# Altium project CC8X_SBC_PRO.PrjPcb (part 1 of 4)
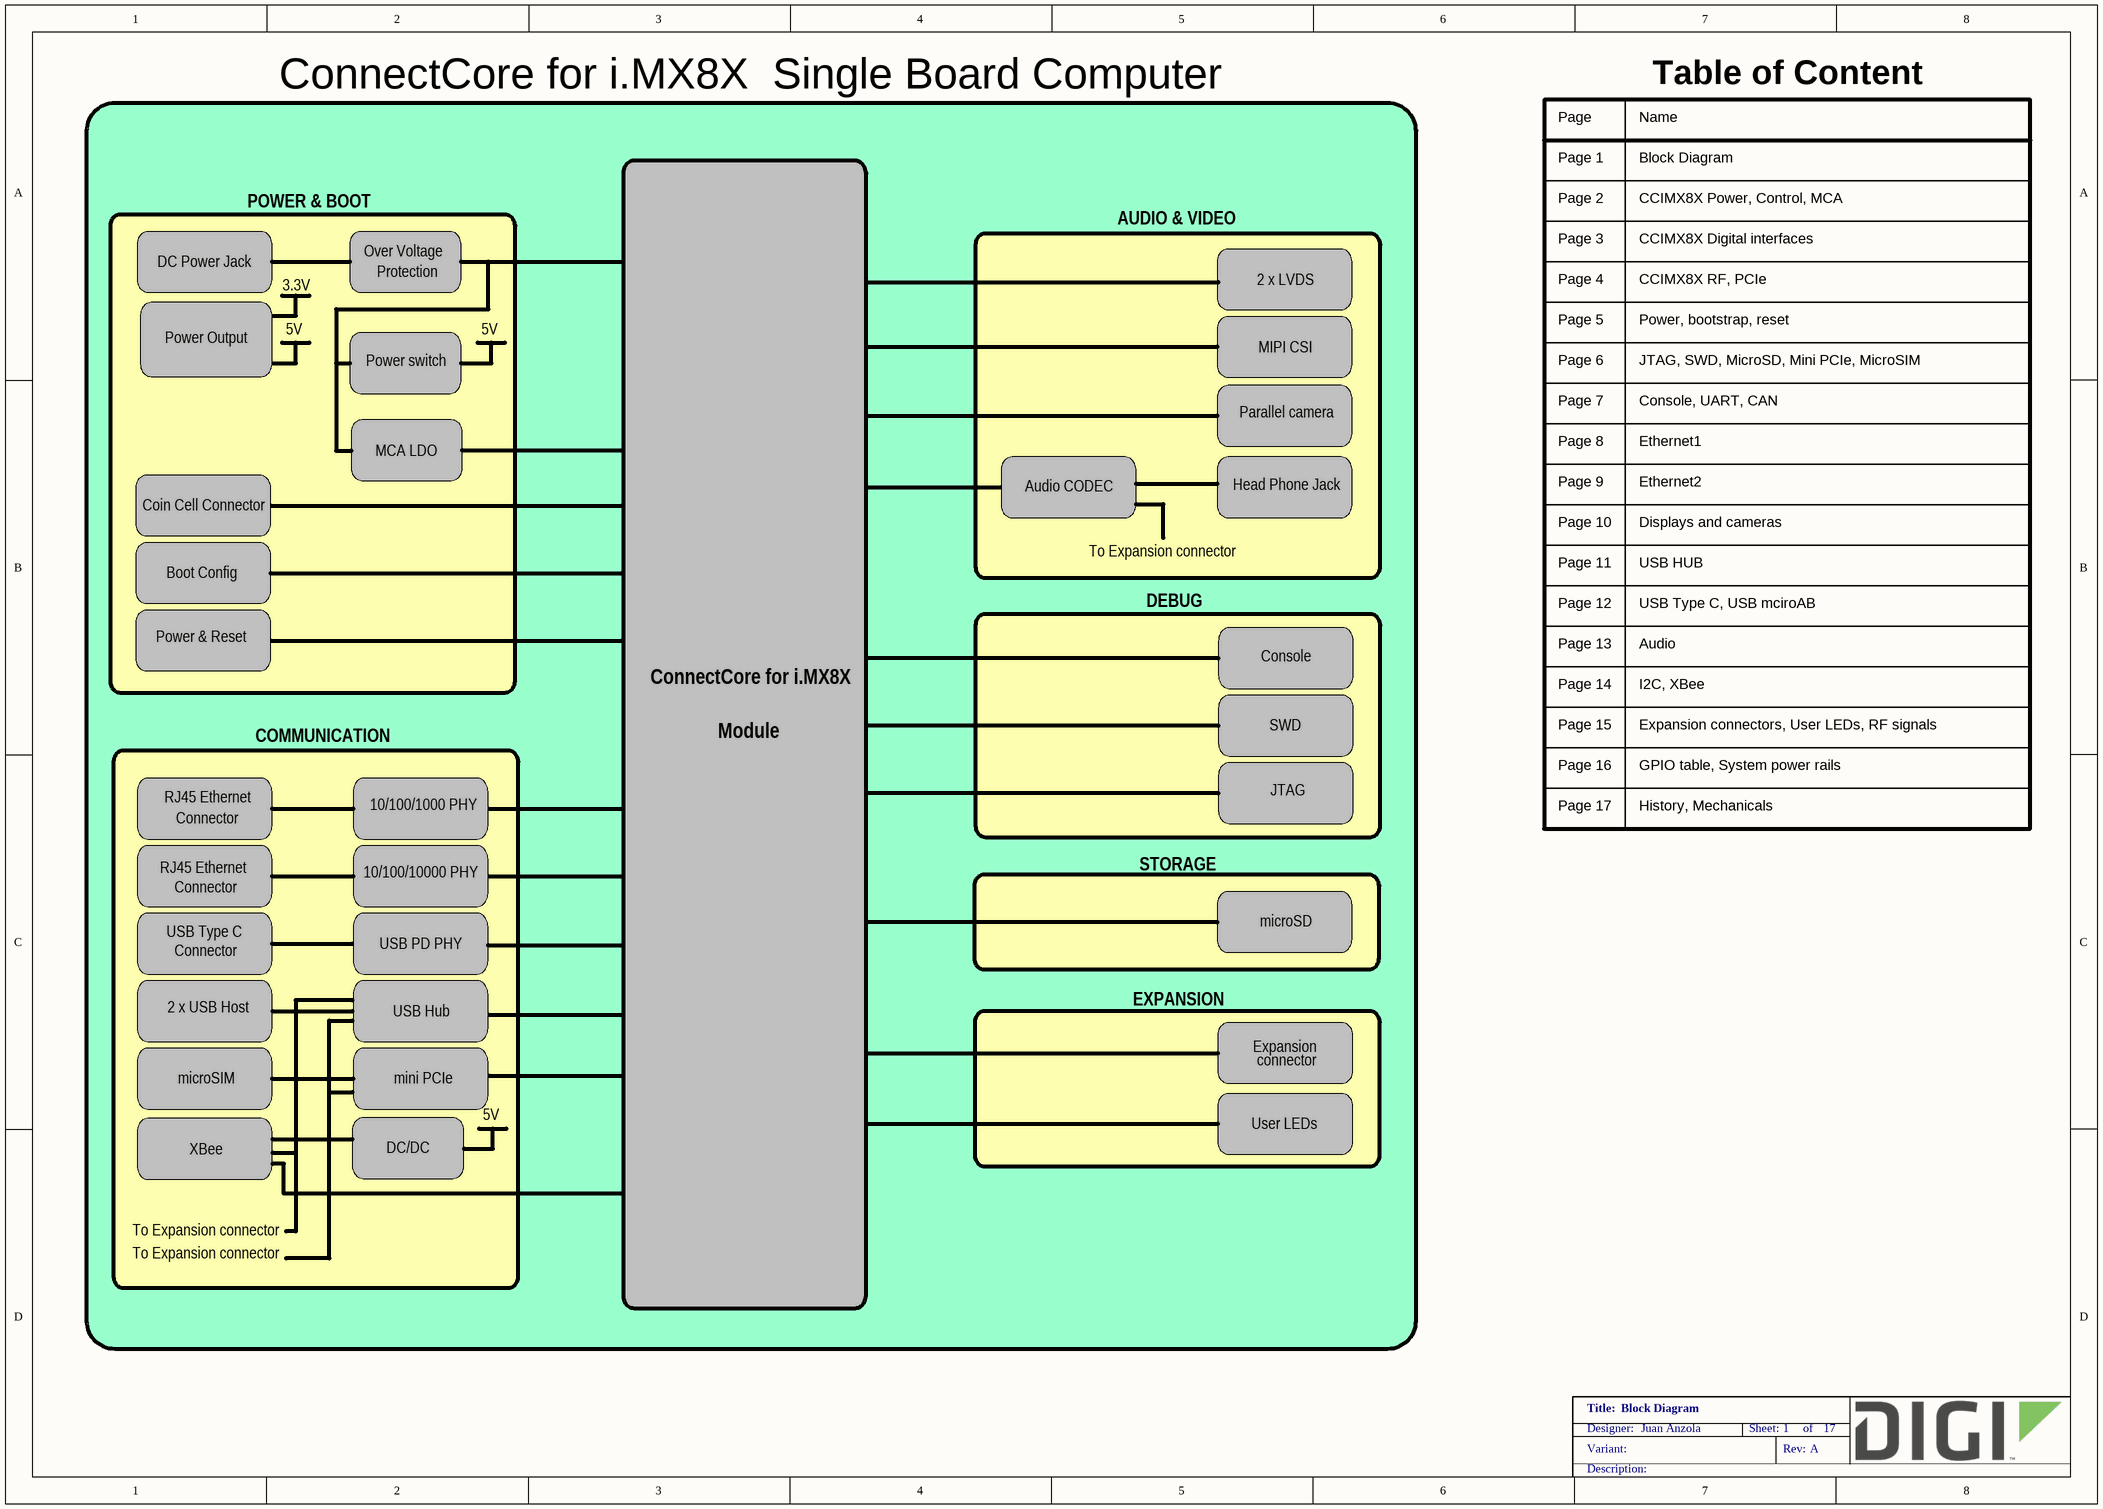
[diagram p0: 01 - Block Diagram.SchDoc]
VariantRevision: A
17 sheets, 578 parts. Net scope: flat (ports and power ports of the same name join across sheets).
Board file: 30015752-05_A.PcbDoc
Sheets:
  01 - Block Diagram.SchDoc
  02 - CCIMX8X Power, Control, MCA.SchDoc
  03 - CCIMX8X Digital interfaces.SchDoc
  04 - CCIMX8X RF, PCIe.SchDoc
  05 - Power, bootstrap, reset.SchDoc
  06 - JTAG, SWD, MicroSD, Mini PCIe, MicroSIM.SchDoc
  07 - Console, UART, CAN.SchDoc
  08 - Ethernet1.SchDoc
  09 - Ethernet2.SchDoc
  10 - Displays and cameras.SchDoc
  11 - USB HUB.SchDoc
  12 - USB Type C, USB microAB.SchDoc
  13 - Audio.SchDoc
  14 - I2C, XBee.SchDoc
  15 - Expansion connectors, User LEDs, RF signals.SchDoc
  16 - GPIO Table, System power rails.SchDoc
  17 - History, Mechanicals.SchDoc

## Sheet 01 - Block Diagram.SchDoc: Block Diagram
size A3; PageSetup: Record=PageOptions¦CenterHorizontal=True¦CenterVertical=True¦PrintScale=0.70¦XCorrection=1.00¦YCorrection=1.00¦PrintKind=0¦BorderSize=5000000¦LeftOffset=0¦BottomOffset=0¦Orientation=2¦PaperLength=4200¦PaperWidth=2970¦Scale=100¦PaperSource=7¦PrintQuality=600¦MediaType=1¦DitherType=10¦PaperKind=A4¦PrintScaleMode=1; Author: Juan Anzola; SheetNumber: 1; SheetTotal: 17

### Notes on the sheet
- ConnectCore for i.MX8X  Single Board Computer
- Table of Content
- Page 1
- Page
- Block Diagram
- Name
- POWER & BOOT
- AUDIO & VIDEO
- Page 2
- Page 3
- CCIMX8X Power, Control, MCA
- CCIMX8X Digital interfaces
- DC Power Jack
- 3.3V
- Protection
- Over Voltage
- 2 x LVDS
- Page 4
- CCIMX8X RF, PCIe
- Power Output
- 5V
- Power switch
- MIPI CSI
- Page 5
- Page 6
- JTAG, SWD, MicroSD, Mini PCIe, MicroSIM
- Power, bootstrap, reset
- Parallel camera
- Page 7
- Page 8
- Ethernet1
- Console, UART, CAN
- Coin Cell Connector
- MCA LDO
- Audio CODEC
- Head Phone Jack
- Page 9
- Ethernet2
- Boot Config
- To Expansion connector
- Page 10
- Page 11
- Displays and cameras
- USB HUB
- Power & Reset
- DEBUG
- Page 12
- Page 13
- Audio
- USB Type C, USB mciroAB
- ConnectCore for i.MX8X
- Console
- Page 14
- I2C, XBee
- COMMUNICATION
- Module
- SWD
- Page 15
- Page 16
- Expansion connectors, User LEDs, RF signals
- GPIO table, System power rails
- RJ45 Ethernet
- Connector
- 10/100/1000 PHY
- JTAG
- Page 17
- History, Mechanicals
- 10/100/10000 PHY
- STORAGE
- USB Type C
- USB PD PHY
- microSD
- 2 x USB Host
- USB Hub
- EXPANSION
- Expansion
- microSIM
- mini PCIe
- connector
- XBee
- DC/DC
- User LEDs

## Sheet 02 - CCIMX8X Power, Control, MCA.SchDoc: CCIMX8X Power, Control, MCA
size A3; PageSetup: Record=PageOptions¦CenterHorizontal=True¦CenterVertical=True¦PrintScale=0.70¦XCorrection=1.00¦YCorrection=1.00¦PrintKind=0¦BorderSize=5000000¦LeftOffset=0¦BottomOffset=0¦Orientation=2¦PaperLength=4200¦PaperWidth=2970¦Scale=100¦PaperSource=7¦PrintQuality=600¦MediaType=1¦DitherType=10¦PaperKind=A4¦PrintScaleMode=1; Author: Juan Anzola; SheetNumber: 2; SheetTotal: 17
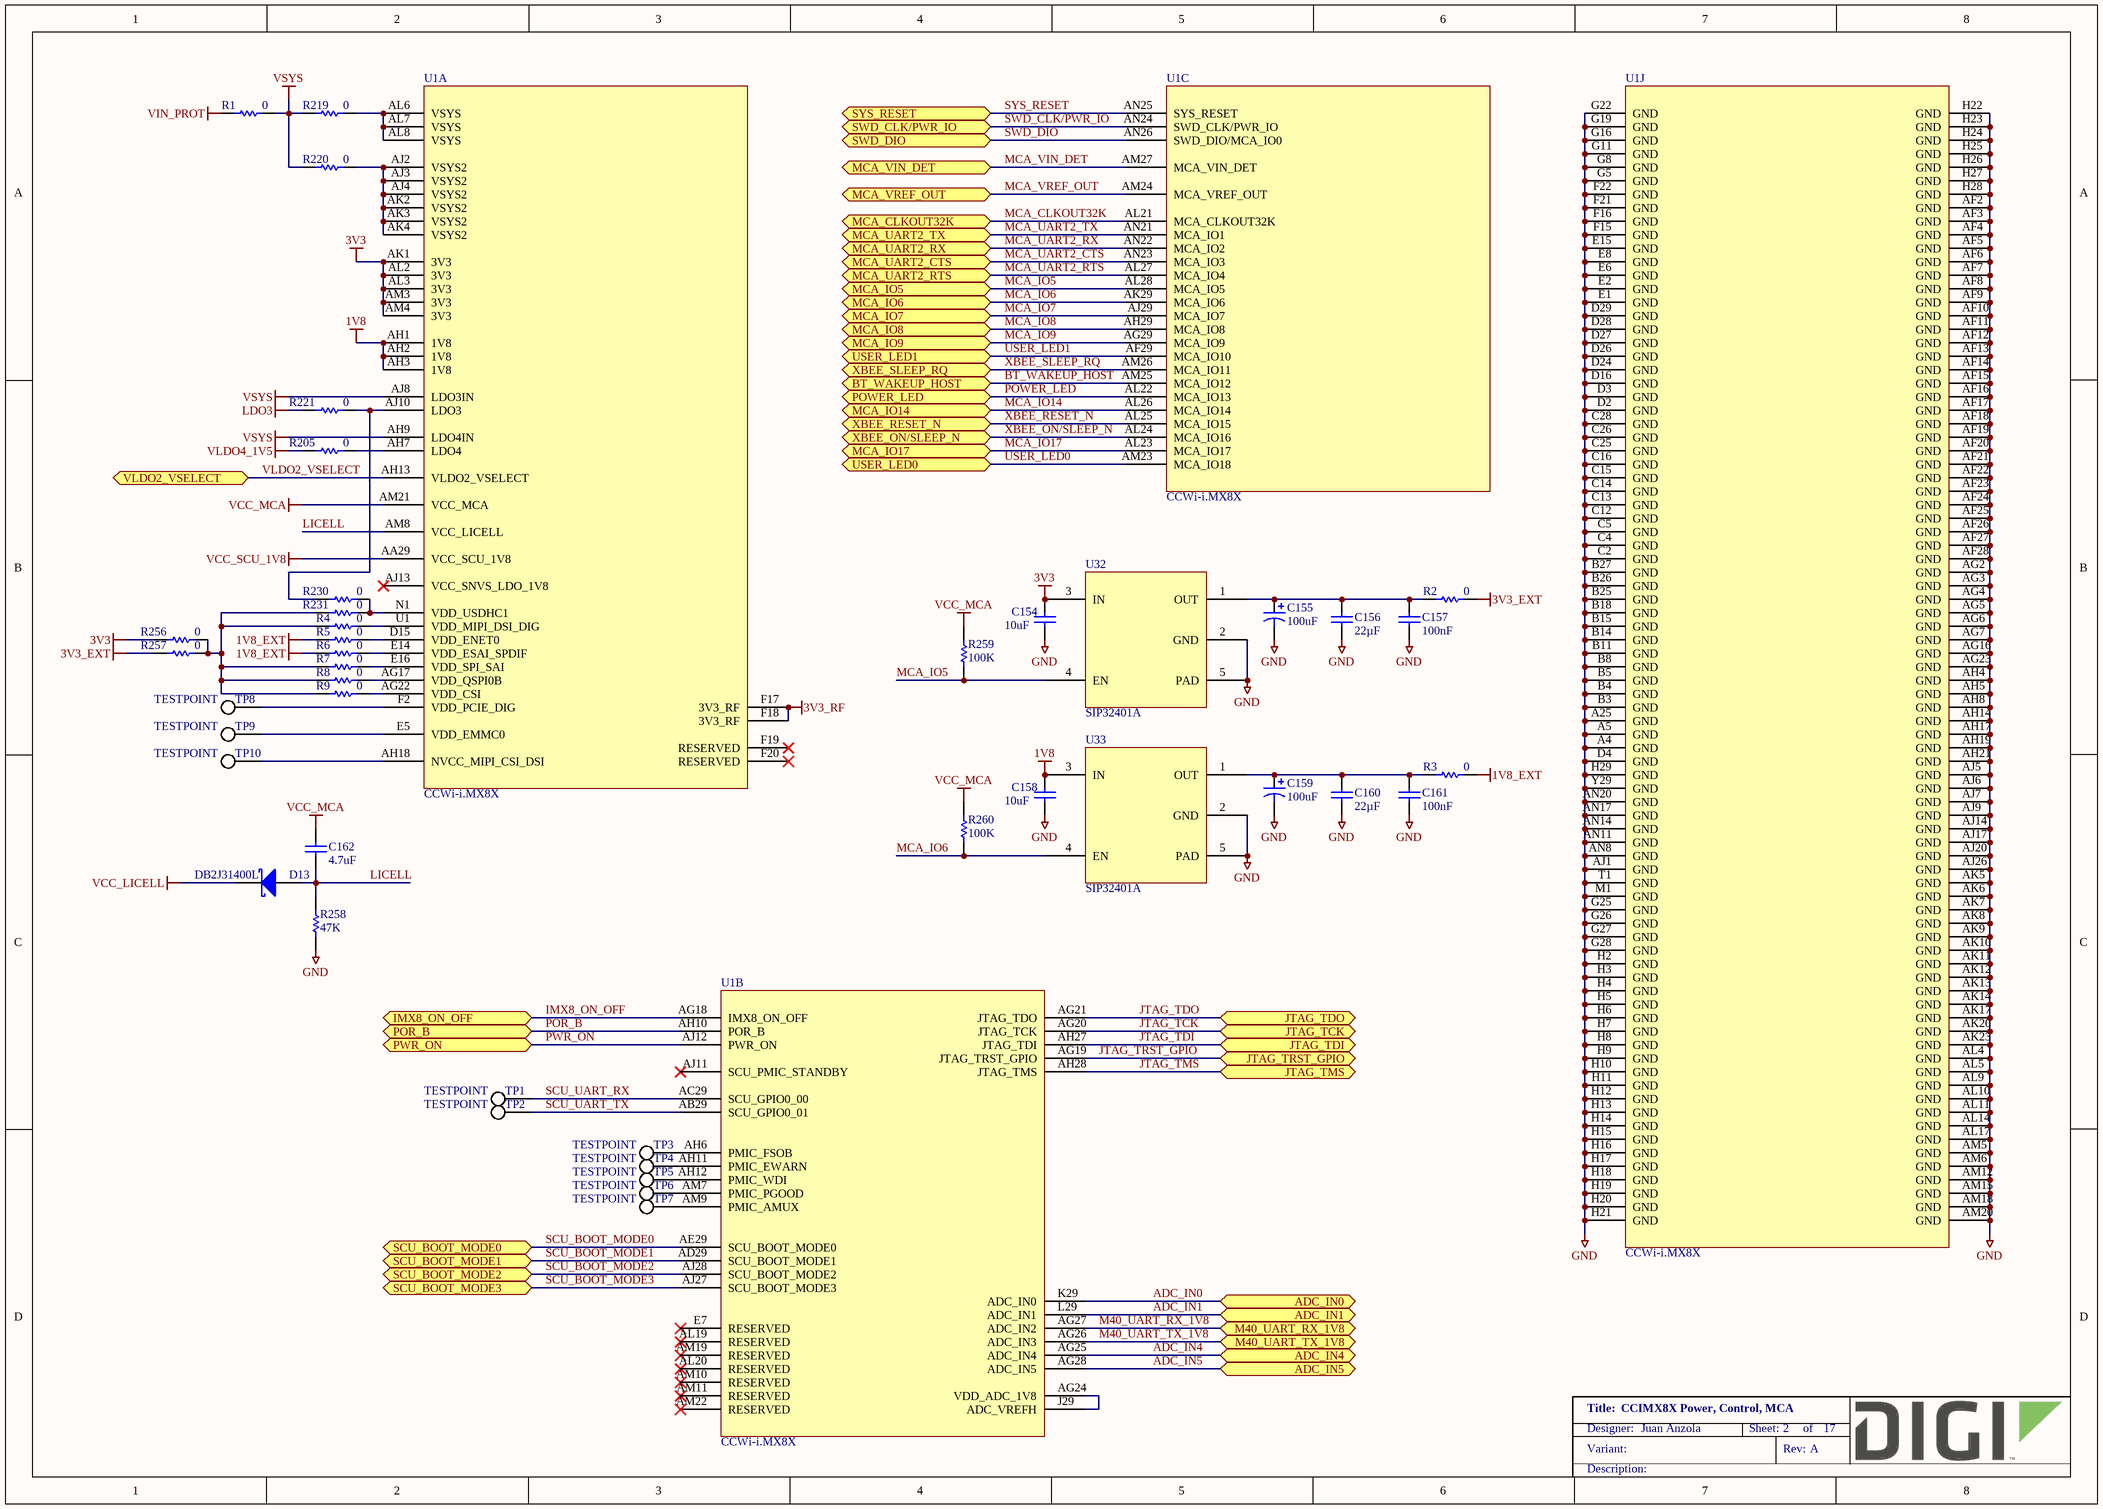
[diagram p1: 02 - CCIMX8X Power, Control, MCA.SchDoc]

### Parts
C154  10uF  [CAPC1005X55N]
C155  100uF  [CAPMP3216X120N]
C156  22µF  [CAPC1608X90N]
C157  100nF  [CAPC1005X55N]
C158  10uF  [CAPC1005X55N]
C159  100uF  [CAPMP3216X120N]
C160  22µF  [CAPC1608X90N]
C161  100nF  [CAPC1005X55N]
C162  4.7uF  [CAPC1005X55N]
D13  DB2J31400L  [SODFL2513X80N]
R1  0  [RESC2013X70N]
R2  0  [RESC1005X40N]
R3  0  [RESC1005X40N]
R4  0  [RESC1005X40N]
R5  0  [RESC1005X40N]
R6  0  [RESC1005X40N]
R7  0  [RESC1005X40N]
R8  0  [RESC1005X40N]
R9  0  [RESC1005X40N]
R205  0  [RESC1005X40N]
R219  0  [RESC1609X55N]
R220  0  [RESC1609X55N]
R221  0  [RESC1005X40N]
R230  0  [RESC1005X40N]
R231  0  [RESC1005X40N]
R256  0  [RESC1005X40N]
R257  0  [RESC1005X40N]
R258  47K  [RESC1005X40N]
R259  100K  [RESC1005X40N]
R260  100K  [RESC1005X40N]
TP1  TESTPOINT  [TP0762]  (no BOM)
TP2  TESTPOINT  [TP0762]  (no BOM)
TP3  TESTPOINT  [TP0762]  (no BOM)
TP4  TESTPOINT  [TP0762]  (no BOM)
TP5  TESTPOINT  [TP0762]  (no BOM)
TP6  TESTPOINT  [TP0762]  (no BOM)
TP7  TESTPOINT  [TP0762]  (no BOM)
TP8  TESTPOINT  [TP0762]  (no BOM)
TP9  TESTPOINT  [TP0762]  (no BOM)
TP10  TESTPOINT  [TP0762]  (no BOM)
U1  CCWi-i.MX8X  [CC8X_LGA]  (parts A,B,C,J of 10)
U32  SIP32401A  [SON50P120X160X60-5T55X91N]
U33  SIP32401A  [SON50P120X160X60-5T55X91N]

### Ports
ADC_IN0 (bidir), ADC_IN1 (bidir), ADC_IN4 (bidir), ADC_IN5 (bidir), BT_WAKEUP_HOST (bidir), IMX8_ON_OFF (bidir), JTAG_TCK (bidir), JTAG_TDI (bidir), JTAG_TDO (bidir), JTAG_TMS (bidir), JTAG_TRST_GPIO (bidir), M40_UART_RX_1V8 (bidir), M40_UART_TX_1V8 (bidir), MCA_CLKOUT32K (bidir), MCA_IO5 (bidir), MCA_IO6 (bidir), MCA_IO7 (bidir), MCA_IO8 (bidir), MCA_IO9 (bidir), MCA_IO14 (bidir), MCA_IO17 (bidir), MCA_UART2_CTS (bidir), MCA_UART2_RTS (bidir), MCA_UART2_RX (bidir), MCA_UART2_TX (bidir), MCA_VIN_DET (bidir), MCA_VREF_OUT (bidir), POR_B (bidir), POWER_LED (bidir), PWR_ON (bidir), SCU_BOOT_MODE0 (bidir), SCU_BOOT_MODE1 (bidir), SCU_BOOT_MODE2 (bidir), SCU_BOOT_MODE3 (bidir), SWD_CLK/PWR_IO (bidir), SWD_DIO (bidir), SYS_RESET (bidir), USER_LED0 (bidir), USER_LED1 (bidir), VLDO2_VSELECT (bidir), XBEE_ON/SLEEP_N (bidir), XBEE_RESET_N (bidir), XBEE_SLEEP_RQ (bidir)

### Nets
1V8: C158.2 U1.AH1(1V8) U1.AH2(1V8) U1.AH3(1V8) U33.3(IN)
1V8_EXT: R3.1 R5.1 R6.1
3V3: C154.2 R256.2 U1.AK1(3V3) U1.AL2(3V3) U1.AL3(3V3) U1.AM3(3V3) U1.AM4(3V3) U32.3(IN)
3V3_EXT: R2.1 R257.1
3V3_RF: U1.F17(3V3_RF) U1.F18(3V3_RF)
GND: C154.1 C155.2 C156.1 C157.1 C158.1 C159.2 C160.1 C161.1 R258.1 U1.A4(GND) U1.A5(GND) U1.A25(GND) U1.AF2(GND) U1.AF3(GND) U1.AF4(GND) U1.AF5(GND) U1.AF6(GND) U1.AF7(GND) U1.AF8(GND) U1.AF9(GND) U1.AF10(GND) U1.AF11(GND) U1.AF12(GND) U1.AF13(GND) U1.AF14(GND) U1.AF15(GND) U1.AF16(GND) U1.AF17(GND) U1.AF18(GND) U1.AF19(GND) U1.AF20(GND) U1.AF21(GND) U1.AF22(GND) U1.AF23(GND) U1.AF24(GND) U1.AF25(GND) U1.AF26(GND) U1.AF27(GND) U1.AF28(GND) U1.AG2(GND) U1.AG3(GND) U1.AG4(GND) U1.AG5(GND) U1.AG6(GND) U1.AG7(GND) U1.AG16(GND) U1.AG23(GND) U1.AH4(GND) U1.AH5(GND) U1.AH8(GND) U1.AH14(GND) U1.AH17(GND) U1.AH19(GND) U1.AH21(GND) U1.AJ1(GND) U1.AJ5(GND) U1.AJ6(GND) U1.AJ7(GND) U1.AJ9(GND) U1.AJ14(GND) U1.AJ17(GND) U1.AJ20(GND) U1.AJ26(GND) U1.AK5(GND) U1.AK6(GND) U1.AK7(GND) U1.AK8(GND) U1.AK9(GND) U1.AK10(GND) U1.AK11(GND) U1.AK12(GND) U1.AK13(GND) U1.AK14(GND) U1.AK17(GND) U1.AK20(GND) U1.AK23(GND) U1.AL4(GND) U1.AL5(GND) U1.AL9(GND) U1.AL10(GND) U1.AL11(GND) U1.AL14(GND) U1.AL17(GND) U1.AM5(GND) U1.AM6(GND) U1.AM12(GND) U1.AM15(GND) U1.AM18(GND) U1.AM20(GND) U1.AN8(GND) U1.AN11(GND) U1.AN14(GND) U1.AN17(GND) U1.AN20(GND) U1.B3(GND) U1.B4(GND) U1.B5(GND) U1.B8(GND) U1.B11(GND) U1.B14(GND) U1.B15(GND) U1.B18(GND) U1.B25(GND) U1.B26(GND) U1.B27(GND) U1.C2(GND) U1.C4(GND) U1.C5(GND) U1.C12(GND) U1.C13(GND) U1.C14(GND) U1.C15(GND) U1.C16(GND) U1.C25(GND) U1.C26(GND) U1.C28(GND) U1.D2(GND) U1.D3(GND) U1.D4(GND) U1.D16(GND) U1.D24(GND) U1.D26(GND) U1.D27(GND) U1.D28(GND) U1.D29(GND) U1.E1(GND) U1.E2(GND) U1.E6(GND) U1.E8(GND) U1.E15(GND) U1.F15(GND) U1.F16(GND) U1.F21(GND) U1.F22(GND) U1.G5(GND) U1.G8(GND) U1.G11(GND) U1.G16(GND) U1.G19(GND) U1.G22(GND) U1.G25(GND) U1.G26(GND) U1.G27(GND) U1.G28(GND) U1.H2(GND) U1.H3(GND) U1.H4(GND) U1.H5(GND) U1.H6(GND) U1.H7(GND) U1.H8(GND) U1.H9(GND) U1.H10(GND) U1.H11(GND) U1.H12(GND) U1.H13(GND) U1.H14(GND) U1.H15(GND) U1.H16(GND) U1.H17(GND) U1.H18(GND) U1.H19(GND) U1.H20(GND) U1.H21(GND) U1.H22(GND) U1.H23(GND) U1.H24(GND) U1.H25(GND) U1.H26(GND) U1.H27(GND) U1.H28(GND) U1.H29(GND) U1.M1(GND) U1.T1(GND) U1.Y29(GND) U32.2(GND) U32.5(PAD) U33.2(GND) U33.5(PAD)
LDO3: R221.1
VCC_LICELL: D13.K
VCC_MCA: C162.2 R259.2 R260.2 U1.AM21(VCC_MCA)
VCC_SCU_1V8: U1.AA29(VCC_SCU_1V8)
VIN_PROT: R1.1
VLDO4_1V5: R205.1
VSYS: R1.2 R219.1 R220.1 U1.AH9(LDO4IN) U1.AJ8(LDO3IN)
ADC_IN0: U1.K29(ADC_IN0) ; port ADC_IN0
ADC_IN1: U1.L29(ADC_IN1) ; port ADC_IN1
ADC_IN4: U1.AG25(ADC_IN4) ; port ADC_IN4
ADC_IN5: U1.AG28(ADC_IN5) ; port ADC_IN5
BT_WAKEUP_HOST: U1.AM25(MCA_IO12) ; port BT_WAKEUP_HOST
IMX8_ON_OFF: U1.AG18(IMX8_ON_OFF) ; port IMX8_ON_OFF
JTAG_TCK: U1.AG20(JTAG_TCK) ; port JTAG_TCK
JTAG_TDI: U1.AH27(JTAG_TDI) ; port JTAG_TDI
JTAG_TDO: U1.AG21(JTAG_TDO) ; port JTAG_TDO
JTAG_TMS: U1.AH28(JTAG_TMS) ; port JTAG_TMS
JTAG_TRST_GPIO: U1.AG19(JTAG_TRST_GPIO) ; port JTAG_TRST_GPIO
LICELL: C162.1 D13.A R258.2 U1.AM8(VCC_LICELL)
M40_UART_RX_1V8: U1.AG27(ADC_IN2) ; port M40_UART_RX_1V8
M40_UART_TX_1V8: U1.AG26(ADC_IN3) ; port M40_UART_TX_1V8
MCA_CLKOUT32K: U1.AL21(MCA_CLKOUT32K) ; port MCA_CLKOUT32K
MCA_IO5: R259.1 U1.AL28(MCA_IO5) U32.4(EN) ; port MCA_IO5
MCA_IO6: R260.1 U1.AK29(MCA_IO6) U33.4(EN) ; port MCA_IO6
MCA_IO7: U1.AJ29(MCA_IO7) ; port MCA_IO7
MCA_IO8: U1.AH29(MCA_IO8) ; port MCA_IO8
MCA_IO9: U1.AG29(MCA_IO9) ; port MCA_IO9
MCA_IO14: U1.AL26(MCA_IO14) ; port MCA_IO14
MCA_IO17: U1.AL23(MCA_IO17) ; port MCA_IO17
MCA_UART2_CTS: U1.AN23(MCA_IO3) ; port MCA_UART2_CTS
MCA_UART2_RTS: U1.AL27(MCA_IO4) ; port MCA_UART2_RTS
MCA_UART2_RX: U1.AN22(MCA_IO2) ; port MCA_UART2_RX
MCA_UART2_TX: U1.AN21(MCA_IO1) ; port MCA_UART2_TX
MCA_VIN_DET: U1.AM27(MCA_VIN_DET) ; port MCA_VIN_DET
MCA_VREF_OUT: U1.AM24(MCA_VREF_OUT) ; port MCA_VREF_OUT
POR_B: U1.AH10(POR_B) ; port POR_B
POWER_LED: U1.AL22(MCA_IO13) ; port POWER_LED
PWR_ON: U1.AJ12(PWR_ON) ; port PWR_ON
SCU_BOOT_MODE0: U1.AE29(SCU_BOOT_MODE0) ; port SCU_BOOT_MODE0
SCU_BOOT_MODE1: U1.AD29(SCU_BOOT_MODE1) ; port SCU_BOOT_MODE1
SCU_BOOT_MODE2: U1.AJ28(SCU_BOOT_MODE2) ; port SCU_BOOT_MODE2
SCU_BOOT_MODE3: U1.AJ27(SCU_BOOT_MODE3) ; port SCU_BOOT_MODE3
SCU_UART_RX: TP1.1 U1.AC29(SCU_GPIO0_00)
SCU_UART_TX: TP2.1 U1.AB29(SCU_GPIO0_01)
SWD_CLK/PWR_IO: U1.AN24(SWD_CLK/PWR_IO) ; port SWD_CLK/PWR_IO
SWD_DIO: U1.AN26(SWD_DIO/MCA_IO0) ; port SWD_DIO
SYS_RESET: U1.AN25(SYS_RESET) ; port SYS_RESET
USER_LED0: U1.AM23(MCA_IO18) ; port USER_LED0
USER_LED1: U1.AF29(MCA_IO10) ; port USER_LED1
VLDO2_VSELECT: U1.AH13(VLDO2_VSELECT) ; port VLDO2_VSELECT
XBEE_ON/SLEEP_N: U1.AL24(MCA_IO16) ; port XBEE_ON/SLEEP_N
XBEE_RESET_N: U1.AL25(MCA_IO15) ; port XBEE_RESET_N
XBEE_SLEEP_RQ: U1.AM26(MCA_IO11) ; port XBEE_SLEEP_RQ
NetC155_1: C155.1 C156.2 C157.2 R2.2 U32.1(OUT)
NetC159_1: C159.1 C160.2 C161.2 R3.2 U33.1(OUT)
NetR4_1: R4.1 R7.1 R8.1 R9.1 R231.2 R256.1 R257.2
NetR4_2: R4.2 U1.U1(VDD_MIPI_DSI_DIG)
NetR5_2: R5.2 U1.D15(VDD_ENET0)
NetR6_2: R6.2 U1.E14(VDD_ESAI_SPDIF)
NetR7_2: R7.2 U1.E16(VDD_SPI_SAI)
NetR8_2: R8.2 U1.AG17(VDD_QSPI0B)
NetR9_2: R9.2 U1.AG22(VDD_CSI)
NetR205_2: R205.2 U1.AH7(LDO4)
NetR219_2: R219.2 U1.AL6(VSYS) U1.AL7(VSYS) U1.AL8(VSYS)
NetR220_2: R220.2 U1.AJ2(VSYS2) U1.AJ3(VSYS2) U1.AJ4(VSYS2) U1.AK2(VSYS2) U1.AK3(VSYS2) U1.AK4(VSYS2)
NetR221_2: R221.2 R230.1 U1.AJ10(LDO3)
NetR230_2: R230.2 R231.1 U1.N1(VDD_USDHC1)
NetTP3_1: TP3.1 U1.AH6(PMIC_FSOB)
NetTP4_1: TP4.1 U1.AH11(PMIC_EWARN)
NetTP5_1: TP5.1 U1.AH12(PMIC_WDI)
NetTP6_1: TP6.1 U1.AM7(PMIC_PGOOD)
NetTP7_1: TP7.1 U1.AM9(PMIC_AMUX)
NetTP8_1: TP8.1 U1.F2(VDD_PCIE_DIG)
NetTP9_1: TP9.1 U1.E5(VDD_EMMC0)
NetTP10_1: TP10.1 U1.AH18(NVCC_MIPI_CSI_DSI)
NetU1_AG24: U1.AG24(VDD_ADC_1V8) U1.J29(ADC_VREFH)

Not connected (* = marked no-connect by the designer): U1 AJ11(SCU_PMIC_STANDBY)* AJ13(VCC_SNVS_LDO_1V8)* AL19(RESERVED)* AL20(RESERVED)* AM10(RESERVED)* AM11(RESERVED)* AM19(RESERVED)* AM22(RESERVED)* E7(RESERVED)* F19(RESERVED)* F20(RESERVED)*

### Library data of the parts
C154 C158 = 1001168: CAP CER 10UF 10V 20% X5R 0402; Part_Type: Capacitor; Manufacturer: Samsung; Manufacturer_Part_Number: CL05A106MP5NUNC; Digi_PN: 14050689; Component_Life_Cycle_State: Reviewed; Area: 0.95; Project: CCWMX6_SBC board
C155 C159 = 1001196: CAP TANT 100UF 6.3V 20% 1206; Part_Type: Capacitor; Manufacturer: Rohm; Manufacturer_Part_Number: TCTAL0J107M8R; Digi_PN: 14050490; Component_Life_Cycle_State: Reviewed; Area: 8.01; Project: CCWMX6_SBC board
C156 C160 = 1000998: CAP CER 22UF 10V 20% X5R 0603; Part_Type: Capacitor; Manufacturer: Samsung; Manufacturer_Part_Number: CL10A226MP8NUNE; Manufacturer_Alt_1: TDK Corporation; Manufacturer_Alt_1_Part_Number: C1608X5R1A226M080AC; Digi_PN: 14050684; Component_Life_Cycle_State: Reviewed; Area: 2.27; Project: ConnectCore i.MX6 module; Tolerance: 20
C157 C161 = 1000006: CAP 100nF 16V 10% X7R 0402; Part_Type: Capacitor; Manufacturer: Murata; Manufacturer_Part_Number: GRM155R71C104KA88D; Component_Life_Cycle_State: CAD Reviewed; Area: 0.95; Project: KITT; Tolerance: 10; Digi_PN: 14050552
C162 = 1000463: CAP CER 4.7UF 4V 20% X5R 0402; Part_Type: Capacitor; Manufacturer: Taiyo Yuden; Manufacturer_Part_Number: AMK105BJ475MV-F; Digi_PN: 14000071; Component_Life_Cycle_State: Reviewed; Area: 0,95
D13 = 1002592: DIODE SCHOTTKY 30V 30MA SMINI2; Part_Type: Diodes; Manufacturer: Panasonic - ECG; Digi_PN: 17000142; Component_Life_Cycle_State: Reviewed; Area: 6,06; Project: DIGI CC8X SOM
R1 = 1001557: RES 0.0 OHM 1/8W JUMP 0805 SMD; Part_Type: Resistor; Manufacturer: Yageo; Manufacturer_Part_Number: RC0805JR-070RL; Note: 13051095 = Digi No. for GE WDNU; Digi_PN: TR00037; Component_Life_Cycle_State: Reviewed; Area: 5,8; Project: WDNU-II; Power_WV_SRF: 125
R2-R9 R205 R221 R230 R231 R256 R257 = 1000076: RES 0.0 OHM 1/10W 0402 SMD; Part_Type: Resistor; Manufacturer: Panasonic - ECG; Manufacturer_Part_Number: ERJ-2GE0R00X; Digi_PN: 13050387; Component_Life_Cycle_State: Proven; Area: 0,95; Project: Adjustable Foundation; Power_WV_SRF: 10
R219 R220 = 1000208: RES 0.0 OHM 1/10W 0603; Part_Type: Resistor; Manufacturer: Panasonic - ECG; Manufacturer_Part_Number: ERJ-3GEY0R00V; Note: 13051103 = Digi No. for GE WDNU; Digi_PN: 13050568; Component_Life_Cycle_State: Reviewed; Area: 2,5; Project: Adjustable Foundation; Voltage: 75V
R258 = 1001155: RES 47.0K OHM 1/16W 1% 0402 SMD; Part_Type: Resistor; Manufacturer: Vishay Dale; Manufacturer_Part_Number: CRCW040247K0FKED; Digi_PN: 13050646; Component_Life_Cycle_State: Reviewed; Area: 0,95
R259 R260 = 1000480: RES 100K OHM 1/10W 1% 0402 SMD; Part_Type: Resistor; Manufacturer: Panasonic - ECG; Manufacturer_Part_Number: ERJ-2RKF1003X; Digi_PN: 13051063; Component_Life_Cycle_State: CAD Reviewed; Area: 0.95; Project: KITT; Power_WV_SRF: 100
TP1-TP10 = CAD0011: TEST POINT 30MIL PAD SMT; Component_Life_Cycle_State: Reviewed; Area: 0,58; Project: CLC
U1 = 1002581: ConnectCore for i.MX8X module - LGA; Manufacturer: DIGI; Manufacturer_Part_Number: 50001980-01; Digi_PN: CC-WMX-JM8E-NN; Component_Life_Cycle_State: Created; Area: 1800; Project: DIGI CC8X SOM
U32 U33 = 1001857: IC SW W/CTRL SLEW RATE 4TDFN; Manufacturer: Vishay Siliconix; Manufacturer_Part_Number: SIP32401ADNP-T1GE4; Component_Life_Cycle_State: Reviewed; Area: 4.93; Project: CCWMX6_SBC board; Digi_PN: 16052004

## Sheet 03 - CCIMX8X Digital interfaces.SchDoc: CCIMX8X Digital interfaces
size A3; PageSetup: Record=PageOptions¦CenterHorizontal=True¦CenterVertical=True¦PrintScale=0.70¦XCorrection=1.00¦YCorrection=1.00¦PrintKind=0¦BorderSize=5000000¦LeftOffset=0¦BottomOffset=0¦Orientation=2¦PaperLength=4200¦PaperWidth=2970¦Scale=100¦PaperSource=7¦PrintQuality=600¦MediaType=1¦DitherType=10¦PaperKind=A4¦PrintScaleMode=1; Author: Juan Anzola; SheetNumber: 3; SheetTotal: 17
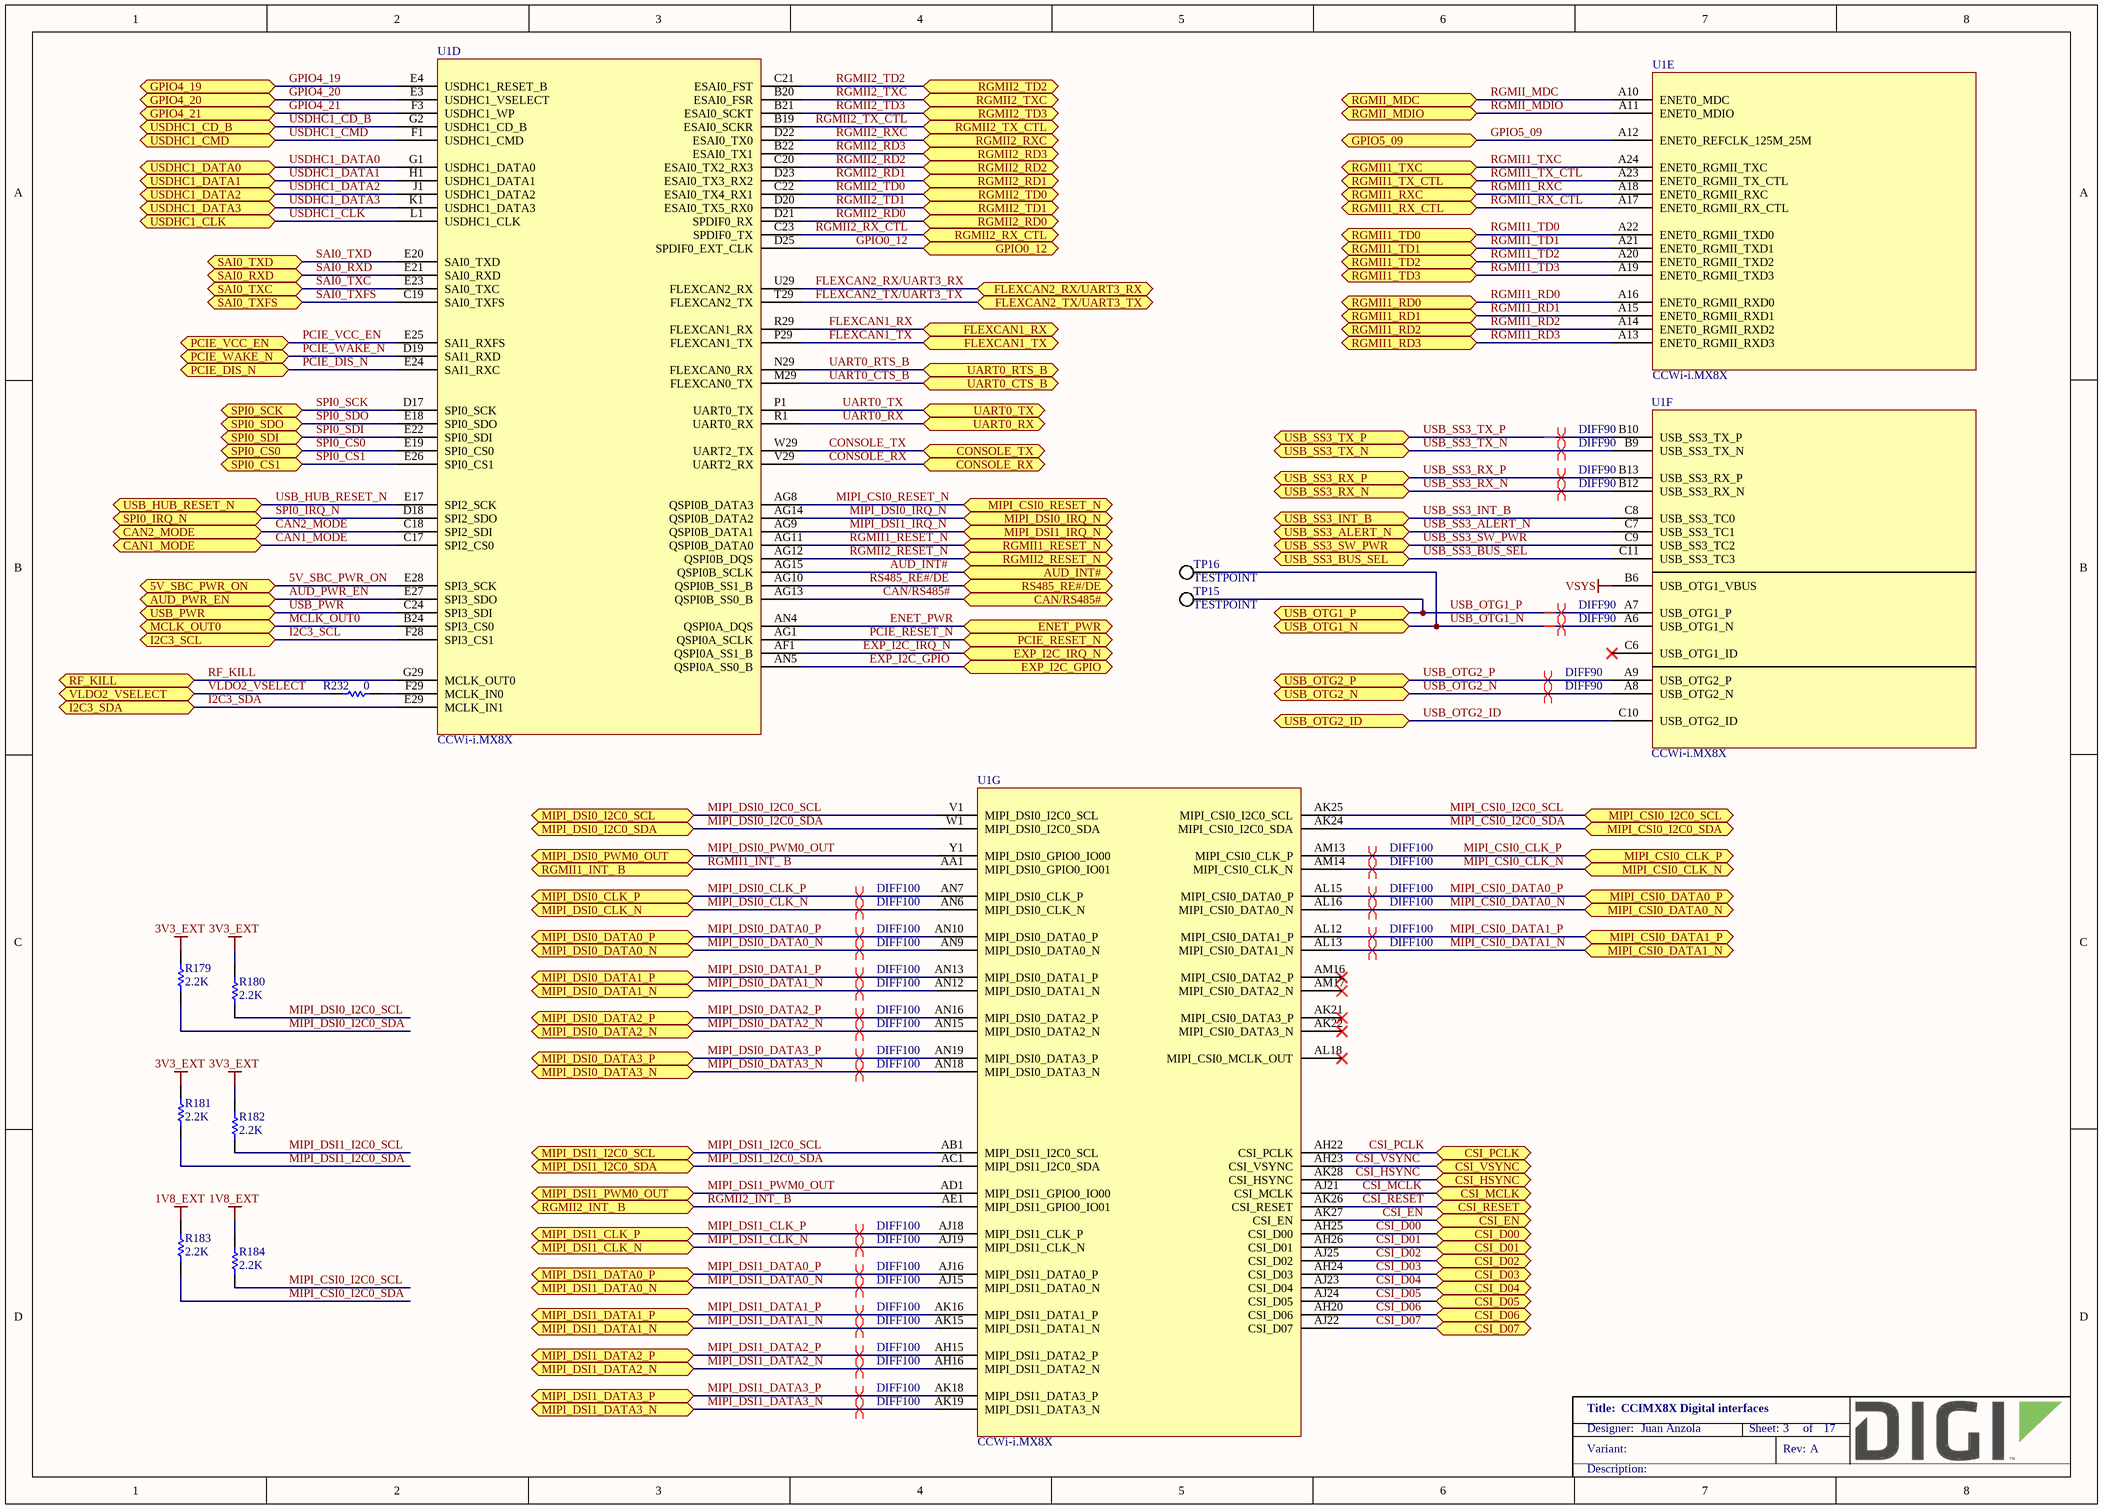
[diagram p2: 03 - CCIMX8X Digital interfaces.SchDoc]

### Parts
R179  2.2K  [RESC1005X40N]
R180  2.2K  [RESC1005X40N]
R181  2.2K  [RESC1005X40N]
R182  2.2K  [RESC1005X40N]
R183  2.2K  [RESC1005X40N]
R184  2.2K  [RESC1005X40N]
R232  0  [RESC1005X40N]
TP15  TESTPOINT  [TP0762]  (no BOM)
TP16  TESTPOINT  [TP0762]  (no BOM)
U1  CCWi-i.MX8X  [CC8X_LGA]  (parts D,E,F,G of 10)

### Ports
5V_SBC_PWR_ON (bidir), AUD_INT# (bidir), AUD_PWR_EN (bidir), CAN1_MODE (bidir), CAN2_MODE (bidir), CAN/RS485# (bidir), CONSOLE_RX (bidir), CONSOLE_TX (bidir), CSI_D00 (bidir), CSI_D01 (bidir), CSI_D02 (bidir), CSI_D03 (bidir), CSI_D04 (bidir), CSI_D05 (bidir), CSI_D06 (bidir), CSI_D07 (bidir), CSI_EN (bidir), CSI_HSYNC (bidir), CSI_MCLK (bidir), CSI_PCLK (bidir), CSI_RESET (bidir), CSI_VSYNC (bidir), ENET_PWR (bidir), EXP_I2C_GPIO (bidir), EXP_I2C_IRQ_N (bidir), FLEXCAN1_RX (bidir), FLEXCAN1_TX (bidir), FLEXCAN2_RX/UART3_RX (bidir), FLEXCAN2_TX/UART3_TX (bidir), GPIO0_12 (bidir), GPIO4_19 (bidir), GPIO4_20 (bidir), GPIO4_21 (bidir), GPIO5_09 (bidir), I2C3_SCL (bidir), I2C3_SDA (bidir), MCLK_OUT0 (bidir), MIPI_CSI0_CLK_N (bidir), MIPI_CSI0_CLK_P (bidir), MIPI_CSI0_DATA0_N (bidir), MIPI_CSI0_DATA0_P (bidir), MIPI_CSI0_DATA1_N (bidir), MIPI_CSI0_DATA1_P (bidir), MIPI_CSI0_I2C0_SCL (bidir), MIPI_CSI0_I2C0_SDA (bidir), MIPI_CSI0_RESET_N (bidir), MIPI_DSI0_CLK_N (bidir), MIPI_DSI0_CLK_P (bidir), MIPI_DSI0_DATA0_N (bidir), MIPI_DSI0_DATA0_P (bidir), MIPI_DSI0_DATA1_N (bidir), MIPI_DSI0_DATA1_P (bidir), MIPI_DSI0_DATA2_N (bidir), MIPI_DSI0_DATA2_P (bidir), MIPI_DSI0_DATA3_N (bidir), MIPI_DSI0_DATA3_P (bidir), MIPI_DSI0_I2C0_SCL (bidir), MIPI_DSI0_I2C0_SDA (bidir), MIPI_DSI0_IRQ_N (bidir), MIPI_DSI0_PWM0_OUT (bidir), MIPI_DSI1_CLK_N (bidir), MIPI_DSI1_CLK_P (bidir), MIPI_DSI1_DATA0_N (bidir), MIPI_DSI1_DATA0_P (bidir), MIPI_DSI1_DATA1_N (bidir), MIPI_DSI1_DATA1_P (bidir), MIPI_DSI1_DATA2_N (bidir), MIPI_DSI1_DATA2_P (bidir), MIPI_DSI1_DATA3_N (bidir), MIPI_DSI1_DATA3_P (bidir), MIPI_DSI1_I2C0_SCL (bidir), MIPI_DSI1_I2C0_SDA (bidir), MIPI_DSI1_IRQ_N (bidir), MIPI_DSI1_PWM0_OUT (bidir), PCIE_DIS_N (bidir), PCIE_RESET_N (bidir), PCIE_VCC_EN (bidir), PCIE_WAKE_N (bidir), RF_KILL (bidir), RGMII1_INT_ B (bidir), RGMII1_RD0 (bidir), RGMII1_RD1 (bidir), RGMII1_RD2 (bidir), RGMII1_RD3 (bidir), RGMII1_RESET_N (bidir), RGMII1_RX_CTL (bidir), RGMII1_RXC (bidir), RGMII1_TD0 (bidir), RGMII1_TD1 (bidir), RGMII1_TD2 (bidir), RGMII1_TD3 (bidir), RGMII1_TX_CTL (bidir), RGMII1_TXC (bidir), RGMII2_INT_ B (bidir), RGMII2_RD0 (bidir), RGMII2_RD1 (bidir), RGMII2_RD2 (bidir), RGMII2_RD3 (bidir), RGMII2_RESET_N (bidir), RGMII2_RX_CTL (bidir), RGMII2_RXC (bidir), RGMII2_TD0 (bidir), RGMII2_TD1 (bidir), RGMII2_TD2 (bidir), RGMII2_TD3 (bidir), RGMII2_TX_CTL (bidir), RGMII2_TXC (bidir), RGMII_MDC (bidir), RGMII_MDIO (bidir), RS485_RE#/DE (bidir), SAI0_RXD (bidir), SAI0_TXC (bidir), SAI0_TXD (bidir), SAI0_TXFS (bidir), SPI0_CS0 (bidir), SPI0_CS1 (bidir), SPI0_IRQ_N (bidir), SPI0_SCK (bidir), SPI0_SDI (bidir), SPI0_SDO (bidir), UART0_CTS_B (bidir), UART0_RTS_B (bidir), UART0_RX (bidir), UART0_TX (bidir), USB_HUB_RESET_N (bidir), USB_OTG1_N (bidir), USB_OTG1_P (bidir), USB_OTG2_ID (bidir), USB_OTG2_N (bidir), USB_OTG2_P (bidir), USB_PWR (bidir), USB_SS3_ALERT_N (bidir), USB_SS3_BUS_SEL (bidir), USB_SS3_INT_B (bidir), USB_SS3_RX_N (bidir), USB_SS3_RX_P (bidir), USB_SS3_SW_PWR (bidir), USB_SS3_TX_N (bidir), USB_SS3_TX_P (bidir), USDHC1_CD_B (bidir), USDHC1_CLK (bidir), USDHC1_CMD (bidir), USDHC1_DATA0 (bidir), USDHC1_DATA1 (bidir), USDHC1_DATA2 (bidir), USDHC1_DATA3 (bidir), VLDO2_VSELECT (bidir)

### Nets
1V8_EXT: R183.2 R184.2
3V3_EXT: R179.2 R180.2 R181.2 R182.2
VSYS: U1.B6(USB_OTG1_VBUS)
5V_SBC_PWR_ON: U1.E28(SPI3_SCK) ; port 5V_SBC_PWR_ON
AUD_INT#: U1.AG15(QSPI0B_SCLK) ; port AUD_INT#
AUD_PWR_EN: U1.E27(SPI3_SDO) ; port AUD_PWR_EN
CAN1_MODE: U1.C17(SPI2_CS0) ; port CAN1_MODE
CAN2_MODE: U1.C18(SPI2_SDI) ; port CAN2_MODE
CAN/RS485#: U1.AG13(QSPI0B_SS0_B) ; port CAN/RS485#
CONSOLE_RX: U1.V29(UART2_RX) ; port CONSOLE_RX
CONSOLE_TX: U1.W29(UART2_TX) ; port CONSOLE_TX
CSI_D00: U1.AH25(CSI_D00) ; port CSI_D00
CSI_D01: U1.AH26(CSI_D01) ; port CSI_D01
CSI_D02: U1.AJ25(CSI_D02) ; port CSI_D02
CSI_D03: U1.AH24(CSI_D03) ; port CSI_D03
CSI_D04: U1.AJ23(CSI_D04) ; port CSI_D04
CSI_D05: U1.AJ24(CSI_D05) ; port CSI_D05
CSI_D06: U1.AH20(CSI_D06) ; port CSI_D06
CSI_D07: U1.AJ22(CSI_D07) ; port CSI_D07
CSI_EN: U1.AK27(CSI_EN) ; port CSI_EN
CSI_HSYNC: U1.AK28(CSI_HSYNC) ; port CSI_HSYNC
CSI_MCLK: U1.AJ21(CSI_MCLK) ; port CSI_MCLK
CSI_PCLK: U1.AH22(CSI_PCLK) ; port CSI_PCLK
CSI_RESET: U1.AK26(CSI_RESET) ; port CSI_RESET
CSI_VSYNC: U1.AH23(CSI_VSYNC) ; port CSI_VSYNC
ENET_PWR: U1.AN4(QSPI0A_DQS) ; port ENET_PWR
EXP_I2C_GPIO: U1.AN5(QSPI0A_SS0_B) ; port EXP_I2C_GPIO
EXP_I2C_IRQ_N: U1.AF1(QSPI0A_SS1_B) ; port EXP_I2C_IRQ_N
FLEXCAN1_RX: U1.R29(FLEXCAN1_RX) ; port FLEXCAN1_RX
FLEXCAN1_TX: U1.P29(FLEXCAN1_TX) ; port FLEXCAN1_TX
FLEXCAN2_RX/UART3_RX: U1.U29(FLEXCAN2_RX) ; port FLEXCAN2_RX/UART3_RX
FLEXCAN2_TX/UART3_TX: U1.T29(FLEXCAN2_TX) ; port FLEXCAN2_TX/UART3_TX
GPIO0_12: U1.D25(SPDIF0_EXT_CLK) ; port GPIO0_12
GPIO4_19: U1.E4(USDHC1_RESET_B) ; port GPIO4_19
GPIO4_20: U1.E3(USDHC1_VSELECT) ; port GPIO4_20
GPIO4_21: U1.F3(USDHC1_WP) ; port GPIO4_21
GPIO5_09: U1.A12(ENET0_REFCLK_125M_25M) ; port GPIO5_09
I2C3_SCL: U1.F28(SPI3_CS1) ; port I2C3_SCL
I2C3_SDA: U1.E29(MCLK_IN1) ; port I2C3_SDA
MCLK_OUT0: U1.B24(SPI3_CS0) ; port MCLK_OUT0
MIPI_CSI0_CLK_N: U1.AM14(MIPI_CSI0_CLK_N) ; port MIPI_CSI0_CLK_N
MIPI_CSI0_CLK_P: U1.AM13(MIPI_CSI0_CLK_P) ; port MIPI_CSI0_CLK_P
MIPI_CSI0_DATA0_N: U1.AL16(MIPI_CSI0_DATA0_N) ; port MIPI_CSI0_DATA0_N
MIPI_CSI0_DATA0_P: U1.AL15(MIPI_CSI0_DATA0_P) ; port MIPI_CSI0_DATA0_P
MIPI_CSI0_DATA1_N: U1.AL13(MIPI_CSI0_DATA1_N) ; port MIPI_CSI0_DATA1_N
MIPI_CSI0_DATA1_P: U1.AL12(MIPI_CSI0_DATA1_P) ; port MIPI_CSI0_DATA1_P
MIPI_CSI0_I2C0_SCL: R184.1 U1.AK25(MIPI_CSI0_I2C0_SCL) ; port MIPI_CSI0_I2C0_SCL
MIPI_CSI0_I2C0_SDA: R183.1 U1.AK24(MIPI_CSI0_I2C0_SDA) ; port MIPI_CSI0_I2C0_SDA
MIPI_CSI0_RESET_N: U1.AG8(QSPI0B_DATA3) ; port MIPI_CSI0_RESET_N
MIPI_DSI0_CLK_N: U1.AN6(MIPI_DSI0_CLK_N) ; port MIPI_DSI0_CLK_N
MIPI_DSI0_CLK_P: U1.AN7(MIPI_DSI0_CLK_P) ; port MIPI_DSI0_CLK_P
MIPI_DSI0_DATA0_N: U1.AN9(MIPI_DSI0_DATA0_N) ; port MIPI_DSI0_DATA0_N
MIPI_DSI0_DATA0_P: U1.AN10(MIPI_DSI0_DATA0_P) ; port MIPI_DSI0_DATA0_P
MIPI_DSI0_DATA1_N: U1.AN12(MIPI_DSI0_DATA1_N) ; port MIPI_DSI0_DATA1_N
MIPI_DSI0_DATA1_P: U1.AN13(MIPI_DSI0_DATA1_P) ; port MIPI_DSI0_DATA1_P
MIPI_DSI0_DATA2_N: U1.AN15(MIPI_DSI0_DATA2_N) ; port MIPI_DSI0_DATA2_N
MIPI_DSI0_DATA2_P: U1.AN16(MIPI_DSI0_DATA2_P) ; port MIPI_DSI0_DATA2_P
MIPI_DSI0_DATA3_N: U1.AN18(MIPI_DSI0_DATA3_N) ; port MIPI_DSI0_DATA3_N
MIPI_DSI0_DATA3_P: U1.AN19(MIPI_DSI0_DATA3_P) ; port MIPI_DSI0_DATA3_P
MIPI_DSI0_I2C0_SCL: R180.1 U1.V1(MIPI_DSI0_I2C0_SCL) ; port MIPI_DSI0_I2C0_SCL
MIPI_DSI0_I2C0_SDA: R179.1 U1.W1(MIPI_DSI0_I2C0_SDA) ; port MIPI_DSI0_I2C0_SDA
MIPI_DSI0_IRQ_N: U1.AG14(QSPI0B_DATA2) ; port MIPI_DSI0_IRQ_N
MIPI_DSI0_PWM0_OUT: U1.Y1(MIPI_DSI0_GPIO0_IO00) ; port MIPI_DSI0_PWM0_OUT
MIPI_DSI1_CLK_N: U1.AJ19(MIPI_DSI1_CLK_N) ; port MIPI_DSI1_CLK_N
MIPI_DSI1_CLK_P: U1.AJ18(MIPI_DSI1_CLK_P) ; port MIPI_DSI1_CLK_P
MIPI_DSI1_DATA0_N: U1.AJ15(MIPI_DSI1_DATA0_N) ; port MIPI_DSI1_DATA0_N
MIPI_DSI1_DATA0_P: U1.AJ16(MIPI_DSI1_DATA0_P) ; port MIPI_DSI1_DATA0_P
MIPI_DSI1_DATA1_N: U1.AK15(MIPI_DSI1_DATA1_N) ; port MIPI_DSI1_DATA1_N
MIPI_DSI1_DATA1_P: U1.AK16(MIPI_DSI1_DATA1_P) ; port MIPI_DSI1_DATA1_P
MIPI_DSI1_DATA2_N: U1.AH16(MIPI_DSI1_DATA2_N) ; port MIPI_DSI1_DATA2_N
MIPI_DSI1_DATA2_P: U1.AH15(MIPI_DSI1_DATA2_P) ; port MIPI_DSI1_DATA2_P
MIPI_DSI1_DATA3_N: U1.AK19(MIPI_DSI1_DATA3_N) ; port MIPI_DSI1_DATA3_N
MIPI_DSI1_DATA3_P: U1.AK18(MIPI_DSI1_DATA3_P) ; port MIPI_DSI1_DATA3_P
MIPI_DSI1_I2C0_SCL: R182.1 U1.AB1(MIPI_DSI1_I2C0_SCL) ; port MIPI_DSI1_I2C0_SCL
MIPI_DSI1_I2C0_SDA: R181.1 U1.AC1(MIPI_DSI1_I2C0_SDA) ; port MIPI_DSI1_I2C0_SDA
MIPI_DSI1_IRQ_N: U1.AG9(QSPI0B_DATA1) ; port MIPI_DSI1_IRQ_N
MIPI_DSI1_PWM0_OUT: U1.AD1(MIPI_DSI1_GPIO0_IO00) ; port MIPI_DSI1_PWM0_OUT
PCIE_DIS_N: U1.E24(SAI1_RXC) ; port PCIE_DIS_N
PCIE_RESET_N: U1.AG1(QSPI0A_SCLK) ; port PCIE_RESET_N
PCIE_VCC_EN: U1.E25(SAI1_RXFS) ; port PCIE_VCC_EN
PCIE_WAKE_N: U1.D19(SAI1_RXD) ; port PCIE_WAKE_N
RF_KILL: U1.G29(MCLK_OUT0) ; port RF_KILL
RGMII1_INT_ B: U1.AA1(MIPI_DSI0_GPIO0_IO01) ; port RGMII1_INT_ B
RGMII1_RD0: U1.A16(ENET0_RGMII_RXD0) ; port RGMII1_RD0
RGMII1_RD1: U1.A15(ENET0_RGMII_RXD1) ; port RGMII1_RD1
RGMII1_RD2: U1.A14(ENET0_RGMII_RXD2) ; port RGMII1_RD2
RGMII1_RD3: U1.A13(ENET0_RGMII_RXD3) ; port RGMII1_RD3
RGMII1_RESET_N: U1.AG11(QSPI0B_DATA0) ; port RGMII1_RESET_N
RGMII1_RX_CTL: U1.A17(ENET0_RGMII_RX_CTL) ; port RGMII1_RX_CTL
RGMII1_RXC: U1.A18(ENET0_RGMII_RXC) ; port RGMII1_RXC
RGMII1_TD0: U1.A22(ENET0_RGMII_TXD0) ; port RGMII1_TD0
RGMII1_TD1: U1.A21(ENET0_RGMII_TXD1) ; port RGMII1_TD1
RGMII1_TD2: U1.A20(ENET0_RGMII_TXD2) ; port RGMII1_TD2
RGMII1_TD3: U1.A19(ENET0_RGMII_TXD3) ; port RGMII1_TD3
RGMII1_TX_CTL: U1.A23(ENET0_RGMII_TX_CTL) ; port RGMII1_TX_CTL
RGMII1_TXC: U1.A24(ENET0_RGMII_TXC) ; port RGMII1_TXC
RGMII2_INT_ B: U1.AE1(MIPI_DSI1_GPIO0_IO01) ; port RGMII2_INT_ B
RGMII2_RD0: U1.D21(SPDIF0_RX) ; port RGMII2_RD0
RGMII2_RD1: U1.D23(ESAI0_TX3_RX2) ; port RGMII2_RD1
RGMII2_RD2: U1.C20(ESAI0_TX2_RX3) ; port RGMII2_RD2
RGMII2_RD3: U1.B22(ESAI0_TX1) ; port RGMII2_RD3
RGMII2_RESET_N: U1.AG12(QSPI0B_DQS) ; port RGMII2_RESET_N
RGMII2_RX_CTL: U1.C23(SPDIF0_TX) ; port RGMII2_RX_CTL
RGMII2_RXC: U1.D22(ESAI0_TX0) ; port RGMII2_RXC
RGMII2_TD0: U1.C22(ESAI0_TX4_RX1) ; port RGMII2_TD0
RGMII2_TD1: U1.D20(ESAI0_TX5_RX0) ; port RGMII2_TD1
RGMII2_TD2: U1.C21(ESAI0_FST) ; port RGMII2_TD2
RGMII2_TD3: U1.B21(ESAI0_SCKT) ; port RGMII2_TD3
RGMII2_TX_CTL: U1.B19(ESAI0_SCKR) ; port RGMII2_TX_CTL
RGMII2_TXC: U1.B20(ESAI0_FSR) ; port RGMII2_TXC
RGMII_MDC: U1.A10(ENET0_MDC) ; port RGMII_MDC
RGMII_MDIO: U1.A11(ENET0_MDIO) ; port RGMII_MDIO
RS485_RE#/DE: U1.AG10(QSPI0B_SS1_B) ; port RS485_RE#/DE
SAI0_RXD: U1.E21(SAI0_RXD) ; port SAI0_RXD
SAI0_TXC: U1.E23(SAI0_TXC) ; port SAI0_TXC
SAI0_TXD: U1.E20(SAI0_TXD) ; port SAI0_TXD
SAI0_TXFS: U1.C19(SAI0_TXFS) ; port SAI0_TXFS
SPI0_CS0: U1.E19(SPI0_CS0) ; port SPI0_CS0
SPI0_CS1: U1.E26(SPI0_CS1) ; port SPI0_CS1
SPI0_IRQ_N: U1.D18(SPI2_SDO) ; port SPI0_IRQ_N
SPI0_SCK: U1.D17(SPI0_SCK) ; port SPI0_SCK
SPI0_SDI: U1.E22(SPI0_SDI) ; port SPI0_SDI
SPI0_SDO: U1.E18(SPI0_SDO) ; port SPI0_SDO
UART0_CTS_B: U1.M29(FLEXCAN0_TX) ; port UART0_CTS_B
UART0_RTS_B: U1.N29(FLEXCAN0_RX) ; port UART0_RTS_B
UART0_RX: U1.R1(UART0_RX) ; port UART0_RX
UART0_TX: U1.P1(UART0_TX) ; port UART0_TX
USB_HUB_RESET_N: U1.E17(SPI2_SCK) ; port USB_HUB_RESET_N
USB_OTG1_N: TP16.1 U1.A6(USB_OTG1_N) ; port USB_OTG1_N
USB_OTG1_P: TP15.1 U1.A7(USB_OTG1_P) ; port USB_OTG1_P
USB_OTG2_ID: U1.C10(USB_OTG2_ID) ; port USB_OTG2_ID
USB_OTG2_N: U1.A8(USB_OTG2_N) ; port USB_OTG2_N
USB_OTG2_P: U1.A9(USB_OTG2_P) ; port USB_OTG2_P
USB_PWR: U1.C24(SPI3_SDI) ; port USB_PWR
USB_SS3_ALERT_N: U1.C7(USB_SS3_TC1) ; port USB_SS3_ALERT_N
USB_SS3_BUS_SEL: U1.C11(USB_SS3_TC3) ; port USB_SS3_BUS_SEL
USB_SS3_INT_B: U1.C8(USB_SS3_TC0) ; port USB_SS3_INT_B
USB_SS3_RX_N: U1.B12(USB_SS3_RX_N) ; port USB_SS3_RX_N
USB_SS3_RX_P: U1.B13(USB_SS3_RX_P) ; port USB_SS3_RX_P
USB_SS3_SW_PWR: U1.C9(USB_SS3_TC2) ; port USB_SS3_SW_PWR
USB_SS3_TX_N: U1.B9(USB_SS3_TX_N) ; port USB_SS3_TX_N
USB_SS3_TX_P: U1.B10(USB_SS3_TX_P) ; port USB_SS3_TX_P
USDHC1_CD_B: U1.G2(USDHC1_CD_B) ; port USDHC1_CD_B
USDHC1_CLK: U1.L1(USDHC1_CLK) ; port USDHC1_CLK
USDHC1_CMD: U1.F1(USDHC1_CMD) ; port USDHC1_CMD
USDHC1_DATA0: U1.G1(USDHC1_DATA0) ; port USDHC1_DATA0
USDHC1_DATA1: U1.H1(USDHC1_DATA1) ; port USDHC1_DATA1
USDHC1_DATA2: U1.J1(USDHC1_DATA2) ; port USDHC1_DATA2
USDHC1_DATA3: U1.K1(USDHC1_DATA3) ; port USDHC1_DATA3
VLDO2_VSELECT: R232.1 ; port VLDO2_VSELECT
NetR232_2: R232.2 U1.F29(MCLK_IN0)

Not connected (* = marked no-connect by the designer): U1 AK21(MIPI_CSI0_DATA3_P)* AK22(MIPI_CSI0_DATA3_N)* AL18(MIPI_CSI0_MCLK_OUT)* AM16(MIPI_CSI0_DATA2_P)* AM17(MIPI_CSI0_DATA2_N)* C6(USB_OTG1_ID)*

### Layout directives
differential pair; net class DIFF100: MIPI_CSI0_CLK_N, MIPI_CSI0_CLK_P, MIPI_CSI0_DATA0_N, MIPI_CSI0_DATA0_P, MIPI_CSI0_DATA1_N, MIPI_CSI0_DATA1_P, MIPI_DSI0_CLK_N, MIPI_DSI0_CLK_P, MIPI_DSI0_DATA0_N, MIPI_DSI0_DATA0_P, MIPI_DSI0_DATA1_N, MIPI_DSI0_DATA1_P, MIPI_DSI0_DATA2_N, MIPI_DSI0_DATA2_P, MIPI_DSI0_DATA3_N, MIPI_DSI0_DATA3_P, MIPI_DSI1_CLK_N, MIPI_DSI1_CLK_P, MIPI_DSI1_DATA0_N, MIPI_DSI1_DATA0_P, MIPI_DSI1_DATA1_N, MIPI_DSI1_DATA1_P, MIPI_DSI1_DATA2_N, MIPI_DSI1_DATA2_P, MIPI_DSI1_DATA3_N, MIPI_DSI1_DATA3_P
differential pair; net class DIFF90: USB_OTG1_N, USB_OTG1_P, USB_OTG2_N, USB_OTG2_P, USB_SS3_RX_N, USB_SS3_RX_P, USB_SS3_TX_N, USB_SS3_TX_P

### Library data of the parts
R179-R184 = 1001156: RES 2.20K OHM 1/16W 1% 0402 SMD; Part_Type: Resistor; Manufacturer: Yageo; Manufacturer_Part_Number: RC0402FR-072K2L; Note: 13051099 = Digi No. for GE WDNU; Digi_PN: 13050699; Component_Life_Cycle_State: Reviewed; Area: 0,95; Project: CCWMX6_SBC board
R232 = 1000076: RES 0.0 OHM 1/10W 0402 SMD; Part_Type: Resistor; Manufacturer: Panasonic - ECG; Manufacturer_Part_Number: ERJ-2GE0R00X; Component_Life_Cycle_State: Proven; Area: 0.95; Project: Adjustable Foundation; Power_WV_SRF: 10; Digi_PN: 13050387
TP15 TP16 = CAD0011: as TP1 on sheet 02 - CCIMX8X Power, Control, MCA
U1 = 1002581: as U1 on sheet 02 - CCIMX8X Power, Control, MCA

## Sheet 04 - CCIMX8X RF, PCIe.SchDoc: CCIMX8X RF, PCIe
size A3; PageSetup: Record=PageOptions¦CenterHorizontal=True¦CenterVertical=True¦PrintScale=0.70¦XCorrection=1.00¦YCorrection=1.00¦PrintKind=0¦BorderSize=5000000¦LeftOffset=0¦BottomOffset=0¦Orientation=2¦PaperLength=4200¦PaperWidth=2970¦Scale=100¦PaperSource=7¦PrintQuality=600¦MediaType=1¦DitherType=10¦PaperKind=A4¦PrintScaleMode=1; Author: Juan Anzola; SheetNumber: 4; SheetTotal: 17
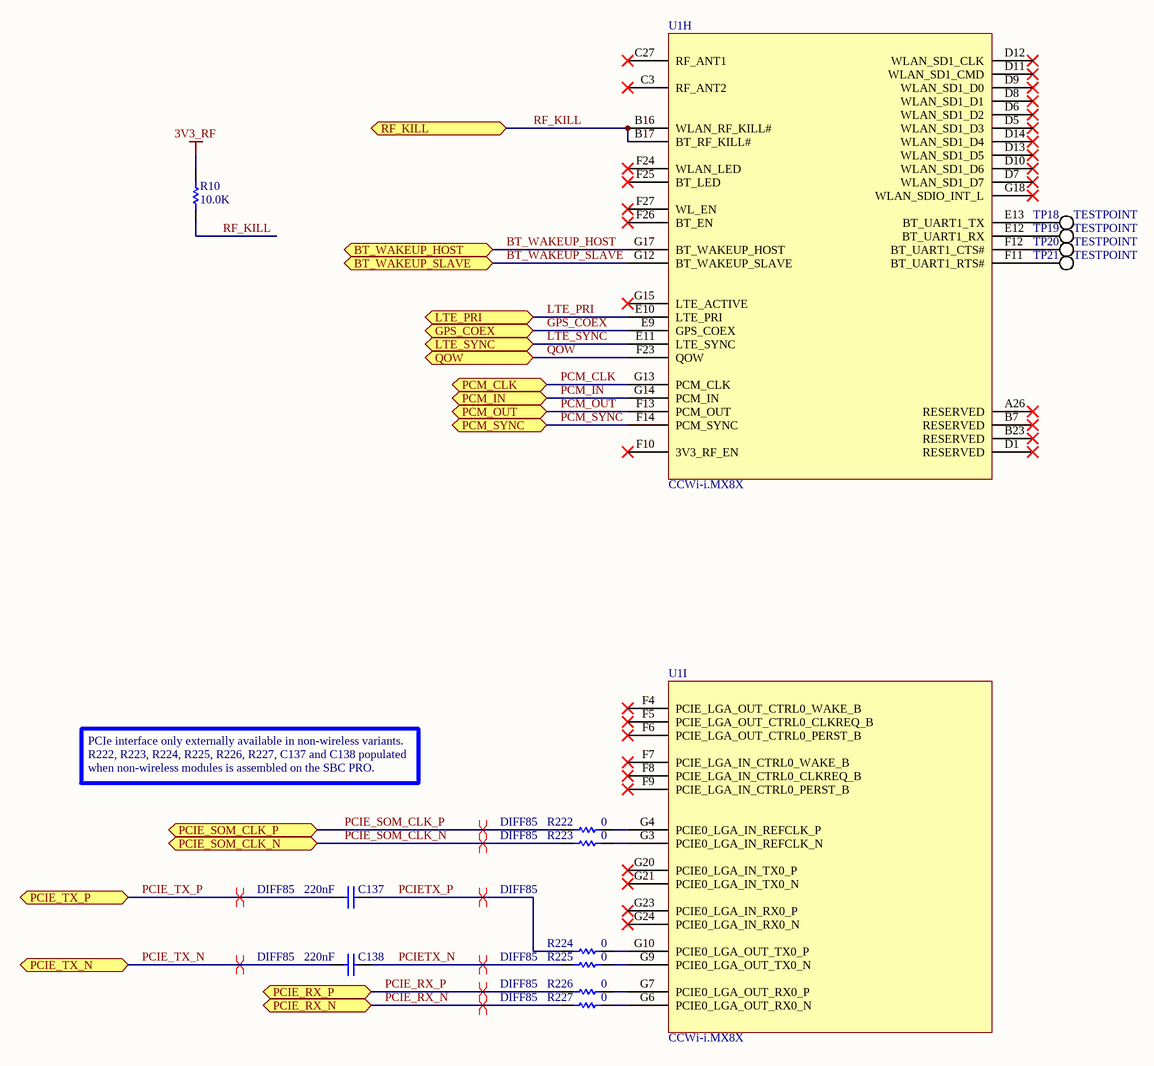
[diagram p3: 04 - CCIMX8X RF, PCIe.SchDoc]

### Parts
C137  220nF  [CAPC0603X33N]
C138  220nF  [CAPC0603X33N]
R10  10.0K  [RESC1005X40N]
R222  0  [RESC1005X40N]
R223  0  [RESC1005X40N]
R224  0  [RESC1005X40N]
R225  0  [RESC1005X40N]
R226  0  [RESC1005X40N]
R227  0  [RESC1005X40N]
TP18  TESTPOINT  [TP0762]  (no BOM)
TP19  TESTPOINT  [TP0762]  (no BOM)
TP20  TESTPOINT  [TP0762]  (no BOM)
TP21  TESTPOINT  [TP0762]  (no BOM)
U1  CCWi-i.MX8X  [CC8X_LGA]  (parts H,I of 10)

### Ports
BT_WAKEUP_HOST (bidir), BT_WAKEUP_SLAVE (bidir), GPS_COEX (bidir), LTE_PRI (bidir), LTE_SYNC (bidir), PCIE_RX_N (bidir), PCIE_RX_P (bidir), PCIE_SOM_CLK_N (bidir), PCIE_SOM_CLK_P (bidir), PCIE_TX_N (bidir), PCIE_TX_P (bidir), PCM_CLK (bidir), PCM_IN (bidir), PCM_OUT (bidir), PCM_SYNC (bidir), QOW (bidir), RF_KILL (bidir)

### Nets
3V3_RF: R10.2
BT_WAKEUP_HOST: U1.G17(BT_WAKEUP_HOST) ; port BT_WAKEUP_HOST
BT_WAKEUP_SLAVE: U1.G12(BT_WAKEUP_SLAVE) ; port BT_WAKEUP_SLAVE
GPS_COEX: U1.E9(GPS_COEX) ; port GPS_COEX
LTE_PRI: U1.E10(LTE_PRI) ; port LTE_PRI
LTE_SYNC: U1.E11(LTE_SYNC) ; port LTE_SYNC
PCIE_RX_N: R227.1 ; port PCIE_RX_N
PCIE_RX_P: R226.1 ; port PCIE_RX_P
PCIE_SOM_CLK_N: R223.1 ; port PCIE_SOM_CLK_N
PCIE_SOM_CLK_P: R222.1 ; port PCIE_SOM_CLK_P
PCIE_TX_N: C138.1 ; port PCIE_TX_N
PCIE_TX_P: C137.1 ; port PCIE_TX_P
PCIETX_N: C138.2 R225.1
PCIETX_P: C137.2 R224.1
PCM_CLK: U1.G13(PCM_CLK) ; port PCM_CLK
PCM_IN: U1.G14(PCM_IN) ; port PCM_IN
PCM_OUT: U1.F13(PCM_OUT) ; port PCM_OUT
PCM_SYNC: U1.F14(PCM_SYNC) ; port PCM_SYNC
QOW: U1.F23(QOW) ; port QOW
RF_KILL: R10.1 U1.B16(WLAN_RF_KILL#) U1.B17(BT_RF_KILL#) ; port RF_KILL
NetR222_2: R222.2 U1.G4(PCIE0_LGA_IN_REFCLK_P)
NetR223_2: R223.2 U1.G3(PCIE0_LGA_IN_REFCLK_N)
NetR224_2: R224.2 U1.G10(PCIE0_LGA_OUT_TX0_P)
NetR225_2: R225.2 U1.G9(PCIE0_LGA_OUT_TX0_N)
NetR226_2: R226.2 U1.G7(PCIE0_LGA_OUT_RX0_P)
NetR227_2: R227.2 U1.G6(PCIE0_LGA_OUT_RX0_N)
NetTP18_1: TP18.1 U1.E13(BT_UART1_TX)
NetTP19_1: TP19.1 U1.E12(BT_UART1_RX)
NetTP20_1: TP20.1 U1.F12(BT_UART1_CTS#)
NetTP21_1: TP21.1 U1.F11(BT_UART1_RTS#)

Not connected (* = marked no-connect by the designer): U1 A26(RESERVED)* B7(RESERVED)* B23(RESERVED)* C3(RF_ANT2)* C27(RF_ANT1)* D1(RESERVED)* D5(WLAN_SD1_D3)* D6(WLAN_SD1_D2)* D7(WLAN_SD1_D7)* D8(WLAN_SD1_D1)* D9(WLAN_SD1_D0)* D10(WLAN_SD1_D6)* D11(WLAN_SD1_CMD)* D12(WLAN_SD1_CLK)* D13(WLAN_SD1_D5)* D14(WLAN_SD1_D4)* F4(PCIE_LGA_OUT_CTRL0_WAKE_B)* F5(PCIE_LGA_OUT_CTRL0_CLKREQ_B)* F6(PCIE_LGA_OUT_CTRL0_PERST_B)* F7(PCIE_LGA_IN_CTRL0_WAKE_B)* F8(PCIE_LGA_IN_CTRL0_CLKREQ_B)* F9(PCIE_LGA_IN_CTRL0_PERST_B)* F10(3V3_RF_EN)* F24(WLAN_LED)* F25(BT_LED)* F26(BT_EN)* F27(WL_EN)* G15(LTE_ACTIVE)* G18(WLAN_SDIO_INT_L)* G20(PCIE0_LGA_IN_TX0_P)* G21(PCIE0_LGA_IN_TX0_N)* G23(PCIE0_LGA_IN_RX0_P)* G24(PCIE0_LGA_IN_RX0_N)*

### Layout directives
differential pair; net class DIFF85: PCIE_RX_N, PCIE_RX_P, PCIE_SOM_CLK_N, PCIE_SOM_CLK_P, PCIE_TX_N, PCIE_TX_P, PCIETX_N, PCIETX_P

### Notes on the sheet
- PCIe interface only externally available in non-wireless variants.
- R222, R223, R224, R225, R226, R227, C137 and C138 populated
- when non-wireless modules is assembled on the SBC PRO.

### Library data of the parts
C137 C138 = 1000963: 220nF, 10V, 20%, 0201; Part_Type: Capacitor; Manufacturer: TDK Corporation; Manufacturer_Part_Number: C0603X5R1A224M030BB; Manufacturer_Alt_1: Taiyo Yuden; Manufacturer_Alt_1_Part_Number: LMK063BJ224MP-F; Manufacturer_Alt_2_Part_Number: 0201ZD224MAT2A; Digi_PN: 14050681; Component_Life_Cycle_State: Reviewed; Area: 0,47; Project: ConnectCore i.MX6 module; Temp_Coef: X5R
R10 = 1000537: RES 10.0K OHM 1/10W 1% 0402 SMD; Part_Type: Resistor; Manufacturer: Panasonic - ECG; Manufacturer_Part_Number: ERJ-2RKF1002X; Digi_PN: 13051084; Component_Life_Cycle_State: CAD Reviewed; Area: 0,95; Project: KITT; Power_WV_SRF: 100
R222-R227 = 1000076: as R2 on sheet 02 - CCIMX8X Power, Control, MCA
TP18-TP21 = CAD0011: as TP1 on sheet 02 - CCIMX8X Power, Control, MCA
U1 = 1002581: as U1 on sheet 02 - CCIMX8X Power, Control, MCA

## Sheet 05 - Power, bootstrap, reset.SchDoc: Power, bootstrap, reset
size A3; PageSetup: Record=PageOptions¦CenterHorizontal=True¦CenterVertical=True¦PrintScale=0.70¦XCorrection=1.00¦YCorrection=1.00¦PrintKind=0¦BorderSize=5000000¦LeftOffset=0¦BottomOffset=0¦Orientation=2¦PaperLength=4200¦PaperWidth=2970¦Scale=100¦PaperSource=7¦PrintQuality=600¦MediaType=1¦DitherType=10¦PaperKind=A4¦PrintScaleMode=1; Author: Juan Anzola; SheetNumber: 5; SheetTotal: 17
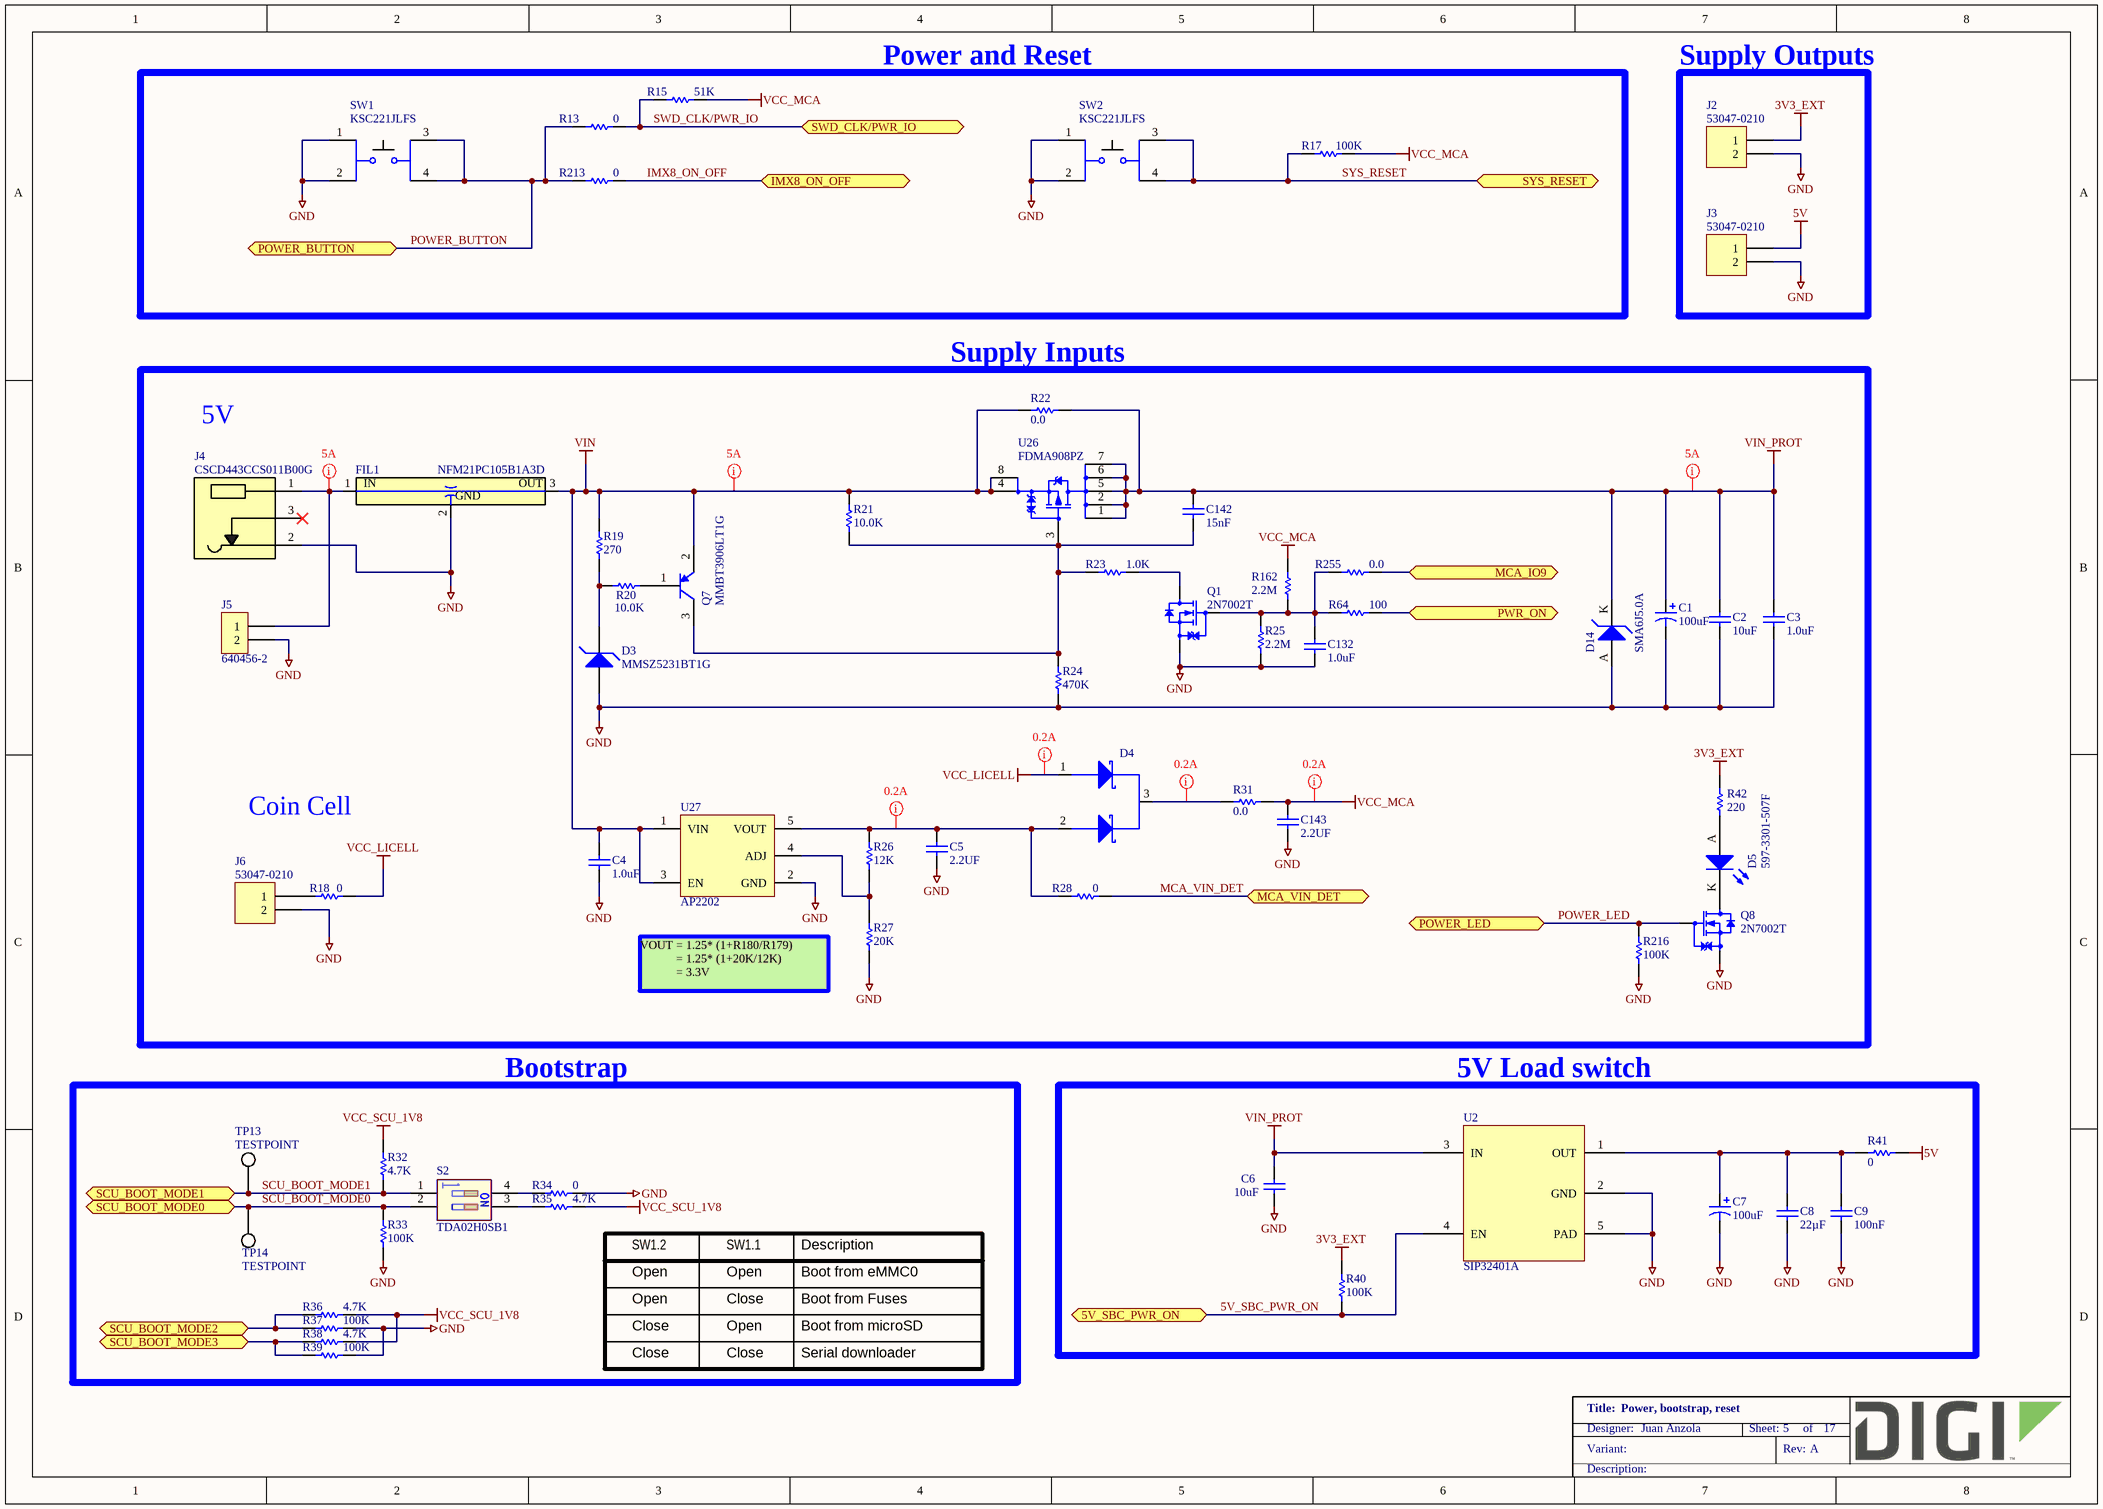
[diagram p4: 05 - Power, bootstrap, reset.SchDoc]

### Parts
C1  100uF  [CAPMP3216X120N]
C2  10uF  [CAPC1005X55N]
C3  1.0uF  [CAPC1005X55N]
C4  1.0uF  [CAPC1005X55L]
C5  2.2UF  [CAPC1608X90N]
C6  10uF  [CAPC1005X55N]
C7  100uF  [CAPMP3216X120N]
C8  22µF  [CAPC1608X90N]
C9  100nF  [CAPC1005X55N]
C132  1.0uF  [CAPC1005X55N]
C142  15nF  [CAPC1005X55N]
C143  2.2UF  [CAPC1608X90N]
D3  MMSZ5231BT1G  [SOD3716X135N]
D4  BAT54CWT1G  [SOT65P210X100-3AN]  (value not drawn)
D5  597-3301-507F  [LEDM3020X130N]
D14  SMA6J5.0A  [DIOM5127X229AN]
FIL1  NFM21PC105B1A3D  [FIL_NFM21P]
J2  Manufacturer_Part_Number: 53047-0210  [MOLEX_53047-0210]  (hidden comment: 1x2P)
J3  Manufacturer_Part_Number: 53047-0210  [MOLEX_53047-0210]  (hidden comment: 1x2P)
J4  CSCD443CCS011B00G  [conn_CSCD443CCS011B00G]
J5  640456-2  [TE_640456-2]
J6  Manufacturer_Part_Number: 53047-0210  [MOLEX_53047-0210]  (hidden comment: 1x2P)
Q1  2N7002T  [SOTFL50P160X80_GSD-3N]
Q7  MMBT3906LT1G  [SOT95P240X110-3N]
Q8  2N7002T  [SOTFL50P160X80_GSD-3N]
R13  0  [RESC1005X40N]
R15  51K  [RESC1005X40N]
R17  100K  [RESC1005X40N]
R18  0  [RESC1005X40N]
R19  270  [RESC2013X70N]
R20  10.0K  [RESC1005X40N]
R21  10.0K  [RESC1005X40N]
R22  0.0  [RESC2013X70N]
R23  1.0K  [RESC1005X40N]
R24  470K  [RESC1005X40N]
R25  2.2M  [RESC1005X40N]
R26  12K  [RESC1609X55N]
R27  20K  [RESC1609X55N]
R28  0  [RESC1005X40N]
R31  0.0  [RESC2013X70N]
R32  4.7K  [RESC1005X40N]
R33  100K  [RESC1005X40N]
R34  0  [RESC1005X40N]
R35  4.7K  [RESC1005X40N]
R36  4.7K  [RESC1005X40N]
R37  100K  [RESC1005X40N]
R38  4.7K  [RESC1005X40N]
R39  100K  [RESC1005X40N]
R40  100K  [RESC1005X40N]
R41  0  [RESC1609X55N]
R42  220  [RESC1005X40N]
R64  100  [RESC1005X40N]
R162  2.2M  [RESC1005X40N]
R213  0  [RESC1005X40N]
R216  100K  [RESC1005X40N]
R255  0.0  [RESC2013X70N]
S2  TDA02H0SB1  [SW_TDA02]
SW1  KSC221JLFS  [SW_KSC221J]
SW2  KSC221JLFS  [SW_KSC221J]
TP13  TESTPOINT  [TP0762]  (no BOM)
TP14  TESTPOINT  [TP0762]  (no BOM)
U2  SIP32401A  [SON50P120X160X60-5T55X91N]
U26  FDMA908PZ  [FAIRCHILD_MICROFET_2X2]
U27  AP2202  [SOT95P280X145-5N]

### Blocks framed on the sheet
Power and Reset: R13 R15 R17 R213 SW1 SW2
Supply Outputs: J2 J3
Supply Inputs: C1-C5 C132 C142 C143 D3-D5 D14 FIL1 J4-J6 Q1 Q7 Q8 R18-R28 R31 R42 R64 R162 R216 R255 U26 U27
Bootstrap: R32-R39 S2 TP13 TP14
5V Load switch: C6-C9 R40 R41 U2

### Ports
5V_SBC_PWR_ON (bidir), IMX8_ON_OFF (bidir), MCA_IO9 (bidir), MCA_VIN_DET (bidir), POWER_BUTTON (bidir), POWER_LED (bidir), PWR_ON (bidir), SCU_BOOT_MODE0 (bidir), SCU_BOOT_MODE1 (bidir), SCU_BOOT_MODE2 (bidir), SCU_BOOT_MODE3 (bidir), SWD_CLK/PWR_IO (bidir), SYS_RESET (bidir)

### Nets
3V3_EXT: J2.1 R40.1 R42.2
5V: J3.1 R41.2
GND: C1.2 C2.1 C3.1 C4.1 C5.1 C6.1 C7.2 C8.1 C9.1 C132.1 C143.1 D3.A D14.A FIL1.2(GND) J2.2 J3.2 J4.2 J5.2 J6.2 Q1.S Q8.S R24.1 R25.1 R27.1 R33.1 R34.2 R37.1 R39.1 R216.2 SW1.1 SW1.2 SW2.1 SW2.2 U2.2(GND) U2.5(PAD) U27.2(GND)
VCC_LICELL: D4.1 R18.1
VCC_MCA: C143.2 R15.2 R17.2 R31.2 R162.2
VCC_SCU_1V8: R32.2 R35.2 R36.1 R38.1
VIN: C4.2 FIL1.3(Output) Q7.2(E) R19.2 R21.2 R22.1 U26.4(S) U26.8(S) U27.1(VIN) U27.3(EN)
VIN_PROT: C1.1 C2.2 C3.2 C6.2 C142.2 D14.K R22.2 U2.3(IN) U26.1(D) U26.2(D) U26.5(D) U26.6(D) U26.7(D)
5V_SBC_PWR_ON: R40.2 U2.4(EN) ; port 5V_SBC_PWR_ON
IMX8_ON_OFF: R213.2 ; port IMX8_ON_OFF
MCA_IO9: R255.2 ; port MCA_IO9
MCA_VIN_DET: R28.2 ; port MCA_VIN_DET
POWER_BUTTON: R13.1 R213.1 SW1.3 SW1.4 ; port POWER_BUTTON
POWER_LED: Q8.G R216.1 ; port POWER_LED
PWR_ON: R64.2 ; port PWR_ON
SCU_BOOT_MODE0: R33.2 S2.2(A2) TP14.1 ; port SCU_BOOT_MODE0
SCU_BOOT_MODE1: R32.1 S2.1(A1) TP13.1 ; port SCU_BOOT_MODE1
SCU_BOOT_MODE2: R36.2 R37.2 ; port SCU_BOOT_MODE2
SCU_BOOT_MODE3: R38.2 R39.2 ; port SCU_BOOT_MODE3
SWD_CLK/PWR_IO: R13.2 R15.1 ; port SWD_CLK/PWR_IO
SYS_RESET: R17.1 SW2.3 SW2.4 ; port SYS_RESET
NetC5_2: C5.2 D4.2 R26.2 R28.1 U27.5(VOUT)
NetC7_1: C7.1 C8.2 C9.2 R41.1 U2.1(OUT)
NetC132_2: C132.2 Q1.G R25.2 R64.1 R162.1 R255.1
NetC142_1: C142.1 Q7.3(C) R21.1 R23.1 R24.2 U26.3(G)
NetD3_K: D3.K R19.1 R20.1
NetD4_3: D4.3 R31.1
NetD5_A: D5.A R42.1
NetD5_K: D5.K Q8.D
NetFIL1_1: FIL1.1(Input) J4.1 J5.1
NetJ6_1: J6.1 R18.2
NetQ1_D: Q1.D R23.2
NetQ7_1: Q7.1(B) R20.2
NetR26_1: R26.1 R27.2 U27.4(ADJ)
NetR34_1: R34.1 S2.4(B1)
NetR35_1: R35.1 S2.3(B2)

Not connected (* = marked no-connect by the designer): J4 3*

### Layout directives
net class 0.2A: NetC5_2, NetD4_3, VCC_LICELL, VCC_MCA
net class 5A: NetFIL1_1, VIN, VIN_PROT

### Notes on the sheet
- 5V
- Coin Cell
- VOUT = 1.25* (1+R180/R179)
  = 1.25* (1+20K/12K)
  = 3.3V
- SW1.2
- SW1.1
- Description
- Open
- Close
- Boot from eMMC0
- Boot from Fuses
- Boot from microSD
- Serial downloader

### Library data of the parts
C1 C7 = 1001196: as C155 on sheet 02 - CCIMX8X Power, Control, MCA
C2 C6 = 1001168: as C154 on sheet 02 - CCIMX8X Power, Control, MCA
C3 C132 = 1001167: CAP CER 1UF 10V 10% X5R 0402; Part_Type: Capacitor; Manufacturer: Murata; Manufacturer_Part_Number: GRM155R61A105KE15D; Digi_PN: 14050399; Component_Life_Cycle_State: Reviewed; Area: 0,95; Project: CCWMX6_SBC board
C4 = 1000073: CAP CER 1UF 6.3V 20% X5R 0402; Part_Type: Capacitor; Manufacturer: Murata; Manufacturer_Part_Number: GRM155R60J105ME19D; Digi_PN: 14050543; Component_Life_Cycle_State: Proven; Area: 0.95; Project: Adjustable Foundation
C5 C143 = 1001303: CAP CER 2.2UF 16V 10% X5R 0603; Part_Type: Capacitor; Manufacturer: TDK Corporation; Manufacturer_Part_Number: C1608X5R1C225K080AB; Digi_PN: 14050730; Component_Life_Cycle_State: Reviewed; Area: 2,27; Project: Pinnacle
C8 = 1000998: as C156 on sheet 02 - CCIMX8X Power, Control, MCA
C9 = 1000006: as C157 on sheet 02 - CCIMX8X Power, Control, MCA
C142 = 1000512: CAP CER 0.015UF 16V 10% X7R 0402; Part_Type: Capacitor; Manufacturer: Murata; Manufacturer_Part_Number: GRM155R71C153KA01D; Digi_PN: 14050713; Component_Life_Cycle_State: CAD Reviewed; Area: 0,95; Project: Cellular Proof of Concept
D3 = 1001494: DIODE ZENER 5.1V 500MW SOD123; Part_Type: Diodes; Manufacturer: On Semiconductor; Digi_PN: 17050700; Component_Life_Cycle_State: Reviewed; Area: 8.28; Project: CCWMX6_SBC board; Note: 17050805 = Digi No. for GE WDNU
D4 = 1000794: DIODE SCHOTTKY 30V 200MA SOT323; Part Number: SDS1920004; Manufacturer: Fairchild Semiconductor; Manufacturer Alt 1: none; Manufacturer Part Num: 0082610201; Part_Type: Diodes; Digi_PN: 17050561; Component_Life_Cycle_State: CAD Reviewed; Area: 7,68; Project: SmartMeter2
D5 = 1001189: LED GREEN 573NM 1208 SMD; Manufacturer: Dialight; Digi_PN: 17050183; Component_Life_Cycle_State: Reviewed; Area: 6; Project: CCWMX6_SBC board; Note: 17050846 = Digi PN for GE WDNU II
D14 = 1002782: SMDIO,TVS UNI-DIR 5V 600W SMA; Part_Type: Diodes; Manufacturer: Vishay Semiconductors; Manufacturer_Part_Number: SMA6J5.0A-M3/5A; Digi_PN: 17000173; Component_Life_Cycle_State: Created; Area: 15.312; Project: DIGI CC8X SOM
FIL1 = 1002768: CAP FEEDTHRU 1UF 20% 10V 0805; Part_Type: Filter; Manufacturer: Murata; Digi_PN: 21000606; Component_Life_Cycle_State: Reviewed; Area: 6.6; Project: DIGI CC8X SOM; Voltage: 10
J2 J3 J6 = 1001136: CONN HEADER 2POS 1.25MM VERT TIN; Part_Type: Connector; Manufacturer: Molex; Component_Life_Cycle_State: Reviewed; Area: 13.6; Project: CCWMX6_SBC board; Digi_PN: 18050343
J4 = 1001105: DC Power Jack; Part_Type: Connector; Manufacturer: Bobbintron Electrical Corp; Digi_PN: 18000302; Component_Life_Cycle_State: Reviewed; Area: 137; Project: CCWMX6_SBC board
J5 = 1002003: CONN HEADER VERT 2POS .100 TIN; Part_Type: Connector; Manufacturer: TE Connectivity; Digi_PN: 18050128; Component_Life_Cycle_State: Created; Area: 29,05; Project: iMX6UL+PMIC
Q1 = 1000715: MOSFET N-CH 60V 115MA SOT-523F; Part_Type: Transistor; Manufacturer: Fairchild Semiconductor; Note: 17050841 = Digi No. for GE WDNU; Digi_PN: 17050797; Component_Life_Cycle_State: CAD Reviewed; Area: 3,06; Project: SmartMeter2
Q7 = 1001204: TRANS GP SS PNP 40V SOT23; Part_Type: IC; Manufacturer: On Semiconductor; Digi_PN: 17050145; Component_Life_Cycle_State: Reviewed; Area: 10.92; Project: CCWMX6_SBC board
Q8 = 1000715: MOSFET N-CH 60V 115MA SOT-523F; Part_Type: Transistor; Manufacturer: Fairchild Semiconductor; Digi_PN: 17050797; Component_Life_Cycle_State: CAD Reviewed; Area: 3.06; Project: SmartMeter2; Note: 17050841 = Digi No. for GE WDNU
R13 R18 R28 R213 = 1000076: as R232 on sheet 03 - CCIMX8X Digital interfaces
R15 = 1001313: RES 51K OHM 1/10W 5% 0402 SMD; Part_Type: Resistor; Manufacturer: Panasonic - ECG; Manufacturer_Part_Number: ERJ-2GEJ513X; Component_Life_Cycle_State: Reviewed; Area: 0,95; Power_WV_SRF: 100; Digi_PN: 13000092
R17 R33 R37 R39 = 1000480: RES 100K OHM 1/10W 1% 0402 SMD; Part_Type: Resistor; Manufacturer: Panasonic - ECG; Manufacturer_Part_Number: ERJ-2RKF1003X; Digi_PN: 13051063; Component_Life_Cycle_State: CAD Reviewed; Area: 0,95; Project: KITT; Power_WV_SRF: 100
R19 = 1001323: RES 270 OHM 1/2W 5% 0805 SMD; Part_Type: Resistor; Manufacturer: Panasonic - ECG; Manufacturer_Part_Number: ERJ-P06J271V; Digi_PN: 13051049; Component_Life_Cycle_State: Reviewed; Area: 4.12; Project: Pinnacle; Power_WV_SRF: 500
R20 R21 = 1000537: RES 10.0K OHM 1/10W 1% 0402 SMD; Part_Type: Resistor; Manufacturer: Panasonic - ECG; Manufacturer_Part_Number: ERJ-2RKF1002X; Digi_PN: 13051084; Component_Life_Cycle_State: CAD Reviewed; Area: 0.95; Project: KITT; Power_WV_SRF: 100
R22 R31 R255 = 1001557: RES 0.0 OHM 1/8W JUMP 0805 SMD; Part_Type: Resistor; Manufacturer: Yageo; Manufacturer_Part_Number: RC0805JR-070RL; Note: 13051095 = Digi No. for GE WDNU; Digi_PN: TR00037; Component_Life_Cycle_State: Reviewed; Area: 5.8; Project: WDNU-II; Power_WV_SRF: 125
R23 = 1000079: RES 1.00K OHM 1/10W 1% 0402 SMD; Part_Type: Resistor; Manufacturer: Panasonic - ECG; Manufacturer_Part_Number: ERJ-2RKF1001X; Digi_PN: 13051085; Component_Life_Cycle_State: Proven; Area: 0,95; Project: Adjustable Foundation; Power_WV_SRF: 10
R24 = 1000701: RES 470K OHM 1/10W 1% 0402 SMD; Part_Type: Resistor; Manufacturer: Panasonic - ECG; Manufacturer_Part_Number: ERJ-2RKF4703X; Component_Life_Cycle_State: CAD Reviewed; Area: 0.95; Project: KITT; Power_WV_SRF: 100; Digi_PN: 13051092
R25 = 1001917: RES SMD 2.2M OHM 5% 1/10W 0402; Part_Type: Resistor; Manufacturer: Panasonic - ECG; Manufacturer_Part_Number: ERJ-2GEJ225X; Digi_PN: 13050820; Component_Life_Cycle_State: Reviewed; Area: 2,27; Project: Powerley Energy Bridge; Power_WV_SRF: 0,1
R26 = 1001200: RES 12.0K OHM 1/10W 1% 0603 SMD; Part_Type: Resistor; Manufacturer: Yageo; Manufacturer_Part_Number: RC0603FR-0712KL; Digi_PN: 13050531; Component_Life_Cycle_State: Reviewed; Area: 2,5; Project: LuCoV2; Power_WV_SRF: 100; Tolerance: 1
R27 = 1000142: RES 20K OHM 1/10W 5% 0603 SMD; Part_Type: Resistor; Manufacturer: Panasonic - ECG; Manufacturer_Part_Number: ERJ-3GEYJ203V; Digi_PN: 13050013; Component_Life_Cycle_State: Reviewed; Area: 2,5; Project: Adjustable Foundation; Power_WV_SRF: 100; Tolerance: 5
R32 R35 R36 R38 = 1000038: RES 4.7K OHM 1/10W 5% 0402 SMD; Part_Type: Resistor; Manufacturer: Panasonic - ECG; Manufacturer_Part_Number: ERJ-2GEJ472X; Digi_PN: 13050549; Component_Life_Cycle_State: Proven; Area: 0,95; Project: Adjustable Foundation; Power_WV_SRF: 100; Tolerance: 5
R34 = 1000076: as R2 on sheet 02 - CCIMX8X Power, Control, MCA
R40 R216 = 1000480: as R259 on sheet 02 - CCIMX8X Power, Control, MCA
R41 = 1000208: RES 0.0 OHM 1/10W 0603; Part_Type: Resistor; Manufacturer: Panasonic - ECG; Manufacturer_Part_Number: ERJ-3GEY0R00V; Note: 13051103 = Digi No. for GE WDNU; Digi_PN: 13050568; Component_Life_Cycle_State: Reviewed; Area: 2.5; Project: Adjustable Foundation; Voltage: 75V
R42 = 1001154: RES 220 OHM 1/16W 1% 0402 SMD; Part_Type: Resistor; Manufacturer: Yageo; Manufacturer_Part_Number: RC0402FR-07220RL; Digi_PN: 13050623; Component_Life_Cycle_State: Reviewed; Area: 0.95; Project: CCWMX6_SBC board
R64 = 1000467: RES 100 OHM 1/10W 1% 0402 SMD; Part_Type: Resistor; Manufacturer: Panasonic - ECG; Manufacturer_Part_Number: ERJ-2RKF1000X; Digi_PN: 13051087; Component_Life_Cycle_State: CAD Reviewed; Area: 0,95; Project: KITT
R162 = 1001917: RES SMD 2.2M OHM 5% 1/10W 0402; Part_Type: Resistor; Manufacturer: Panasonic - ECG; Manufacturer_Part_Number: ERJ-2GEJ225X; Digi_PN: 13050820; Component_Life_Cycle_State: Reviewed; Area: 2.27; Project: Powerley Energy Bridge; Power_WV_SRF: 0.1
S2 = 1001500: SWITCH DIP 2POS HALF PITCH 24V; Manufacturer: C&K Components; Note: 22000296 = Digi No. for GE WDNU; Digi_PN: 22000060; Component_Life_Cycle_State: Reviewed; Area: 34,3; Project: CCWMX6_SBC board
SW1 SW2 = 1001124: SWITCH TACTILE SPST-NO 0.05A 32V; Manufacturer: ITT; Digi_PN: 22000059; Component_Life_Cycle_State: Reviewed; Area: 37; Project: CCWMX6_SBC board; Note: 22000295 = Digi No. for GE WDNU
TP13 TP14 = CAD0011: as TP1 on sheet 02 - CCIMX8X Power, Control, MCA
U2 = 1001857: as U32 on sheet 02 - CCIMX8X Power, Control, MCA
U26 = 1001972: MOSFET P-CH 12V 12A 6QFN; Part_Type: Transistor; Manufacturer: Fairchild Semiconductors; Digi_PN: 17050873; Component_Life_Cycle_State: Reviewed; Area: 9; Project: iMX6UL+PMIC
U27 = 1001979: IC REG LDO ADJ 0.15A SOT25; Part_Type: Regulator; Manufacturer: Diodes, Inc.; Manufacturer_Part_Number: AP2202K-ADJTRG1; Digi_PN: 17050874; Component_Life_Cycle_State: Created; Area: 8,9; Project: iMX6UL+PMIC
